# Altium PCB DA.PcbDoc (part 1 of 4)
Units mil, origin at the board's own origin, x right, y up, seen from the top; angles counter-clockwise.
Board outline 6588.03 x 5423.03 mil, 4 copper layers (Top Layer, GND, VCC, Bottom Layer); 506 components, 345 nets, 1676 pads, 350 vias.
Unrouted connection lines stored in the file: 30.
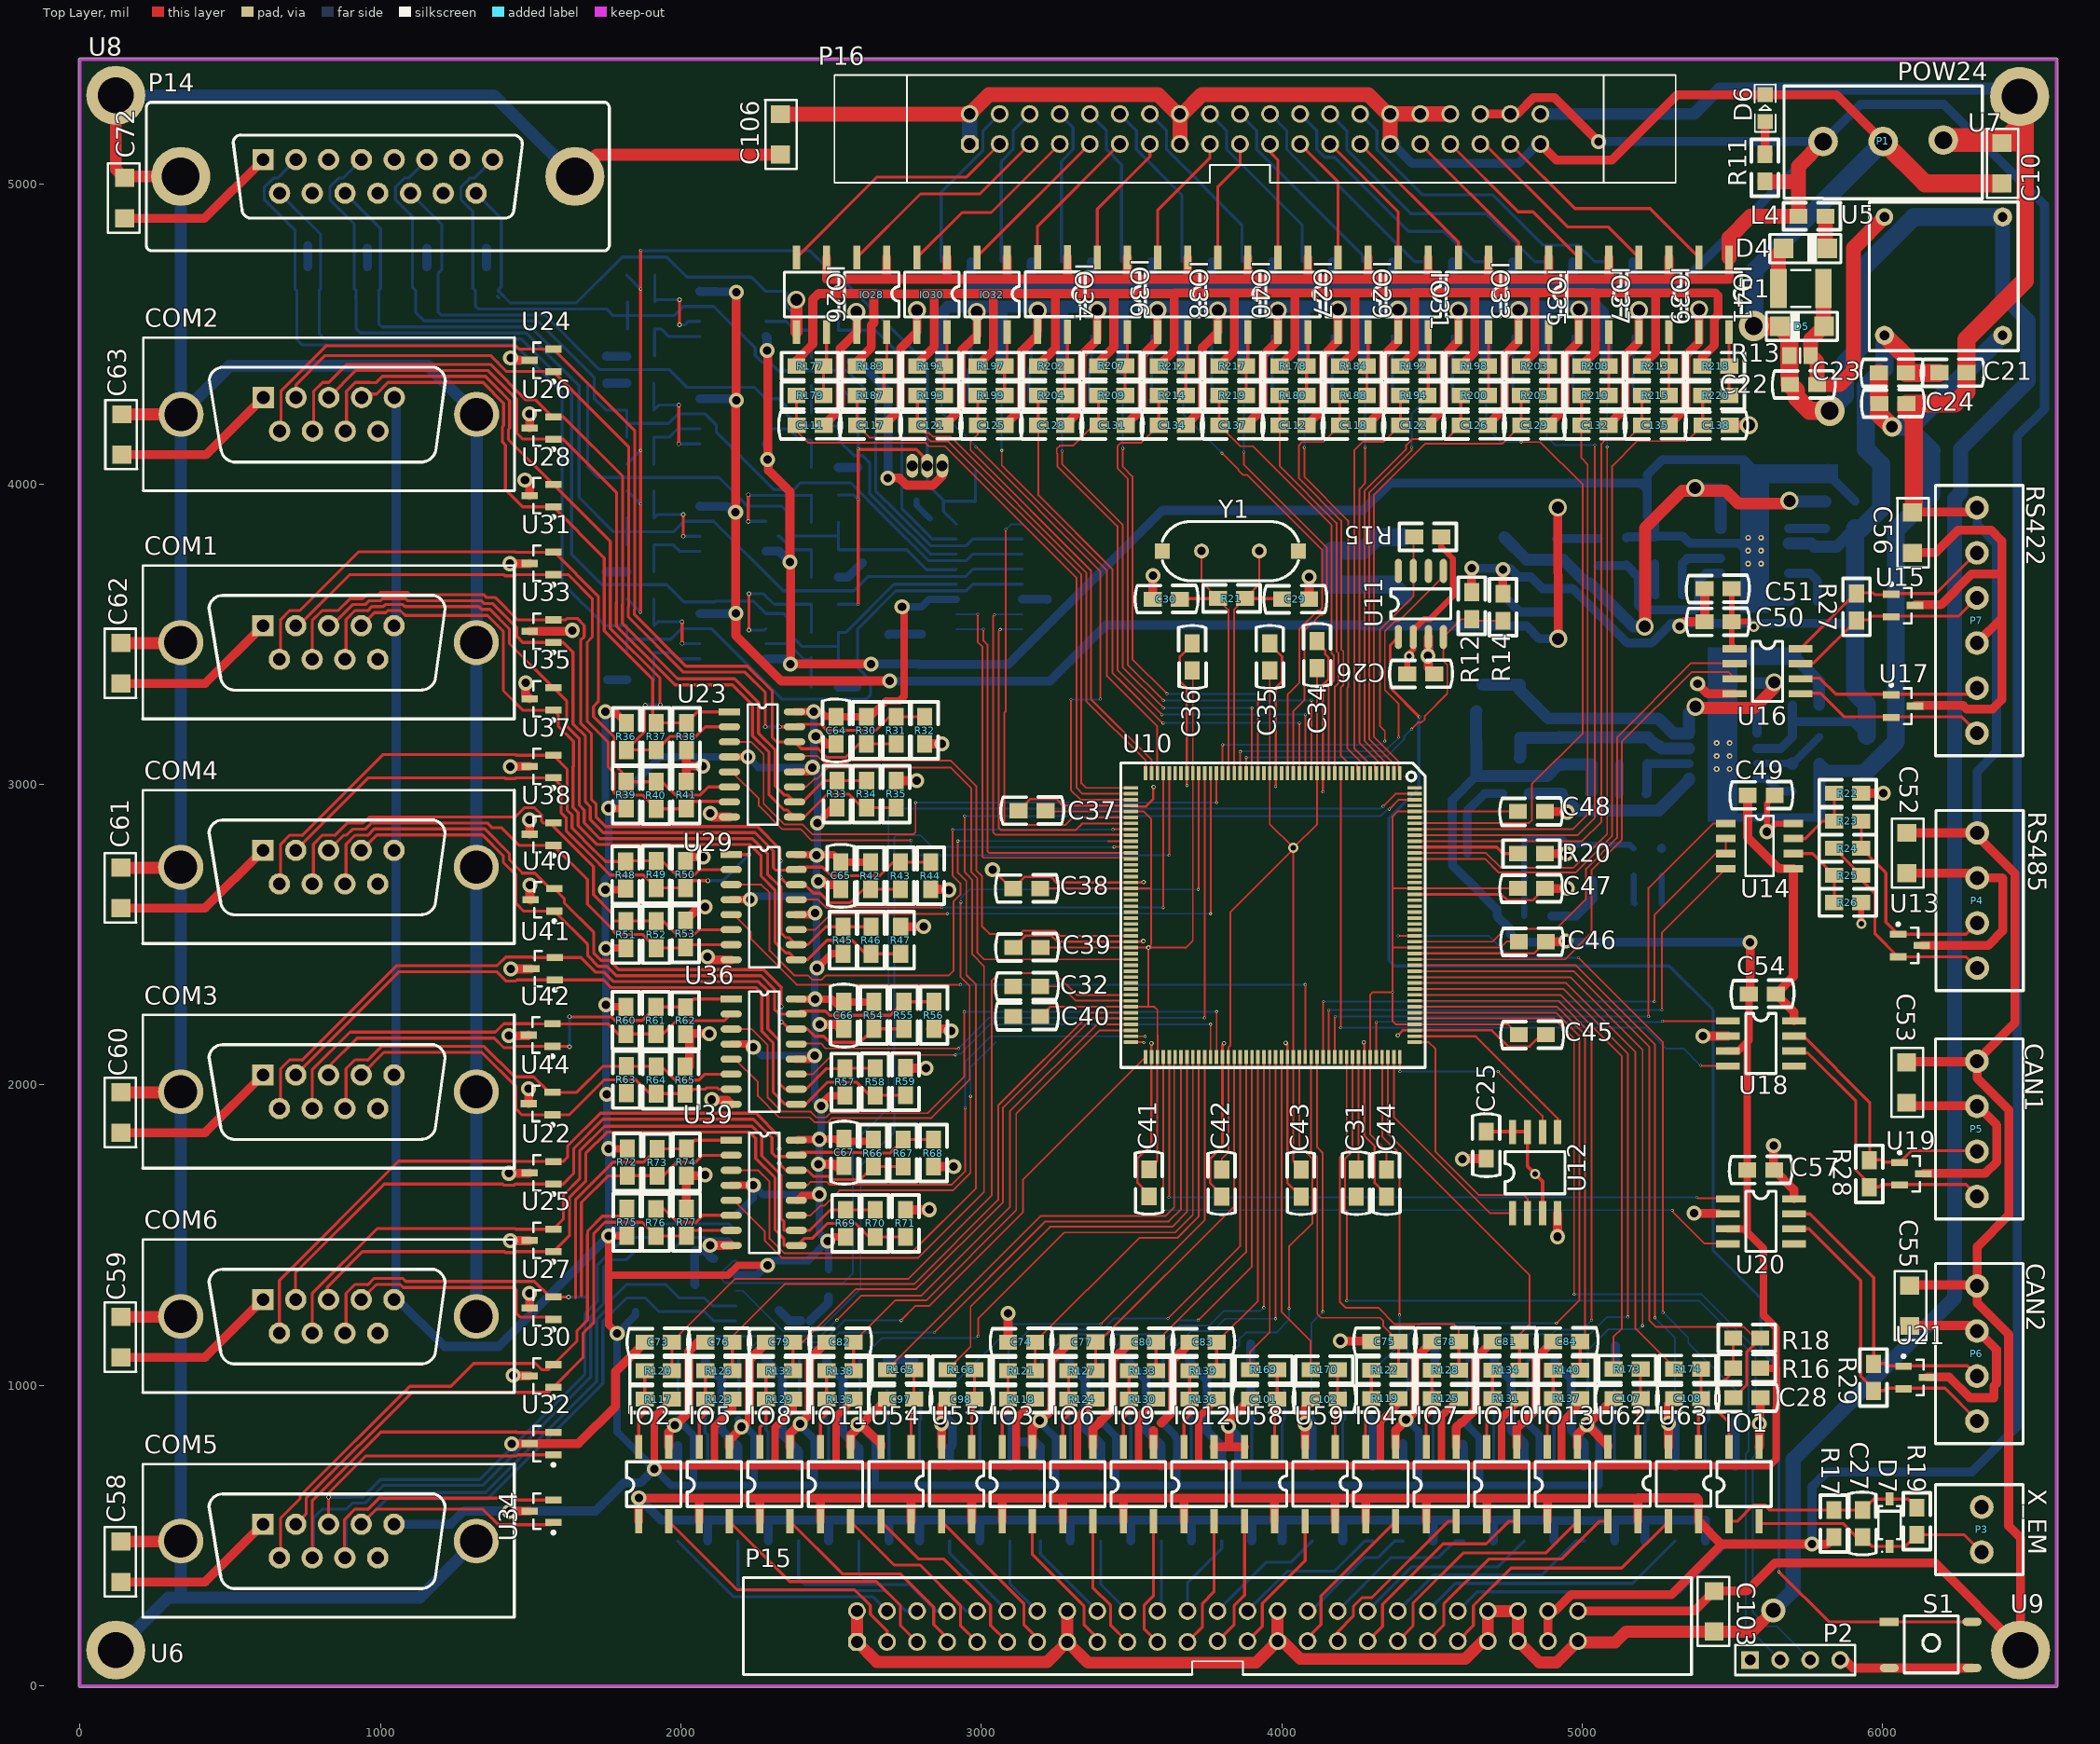
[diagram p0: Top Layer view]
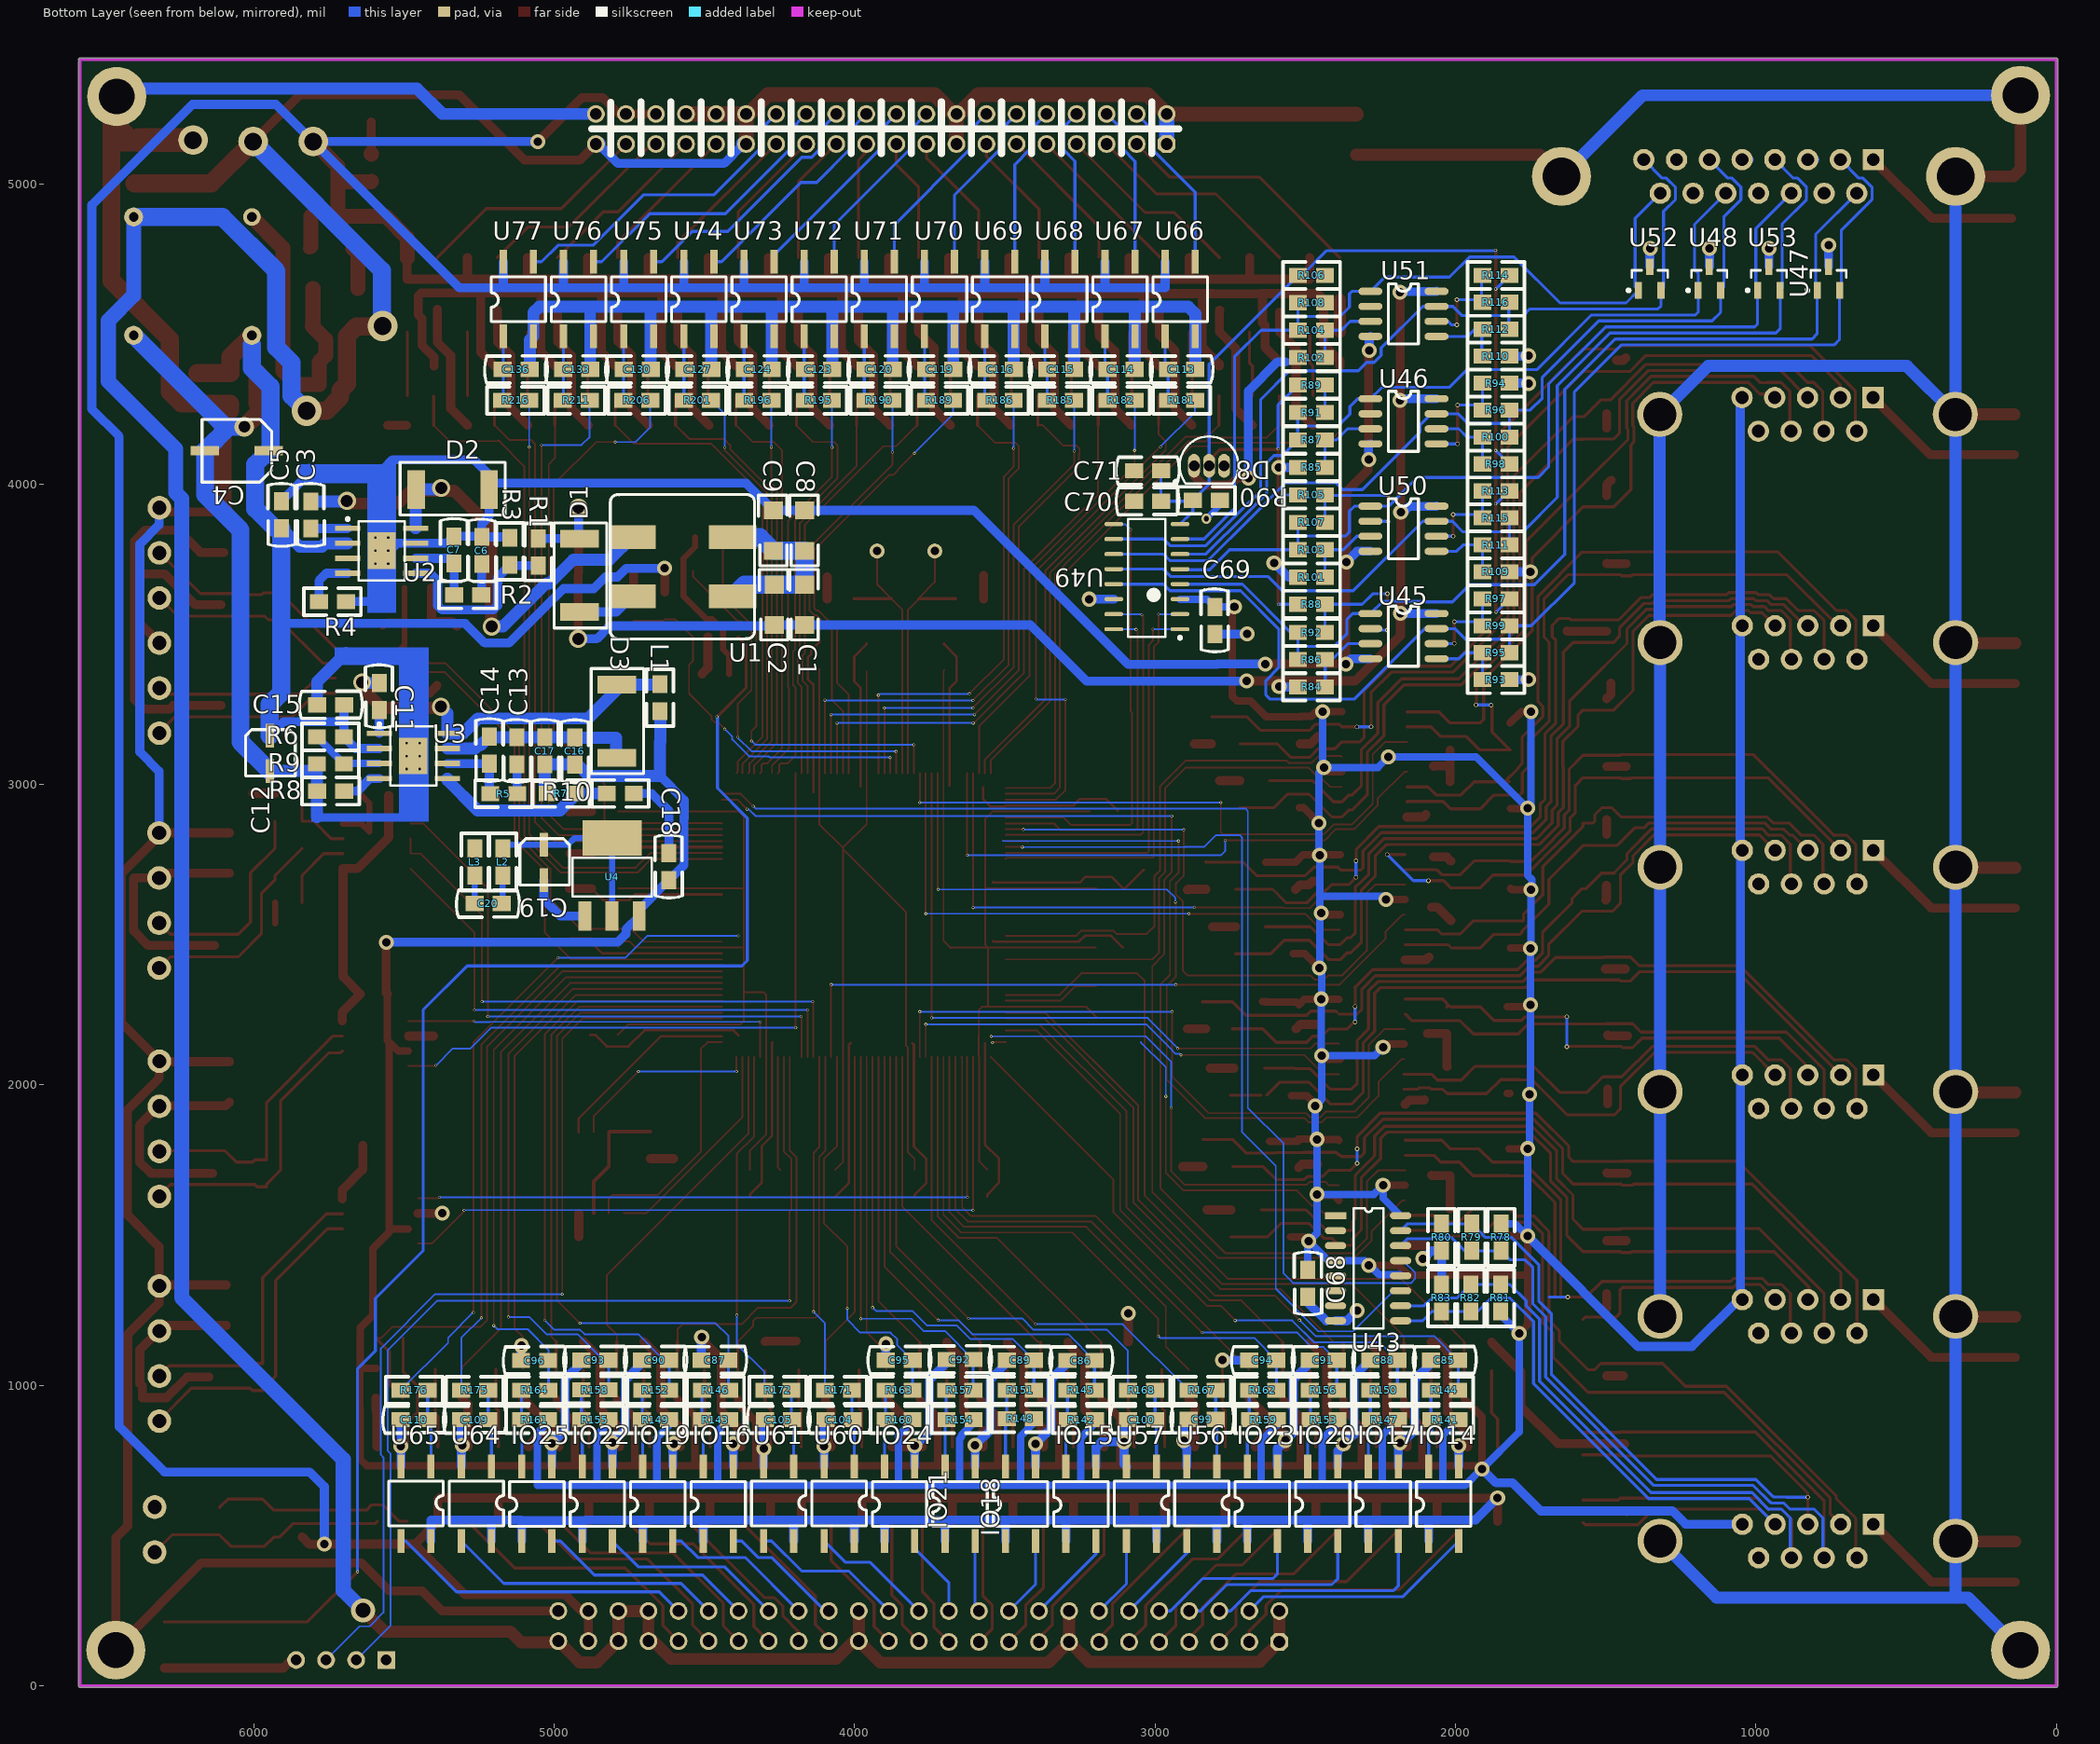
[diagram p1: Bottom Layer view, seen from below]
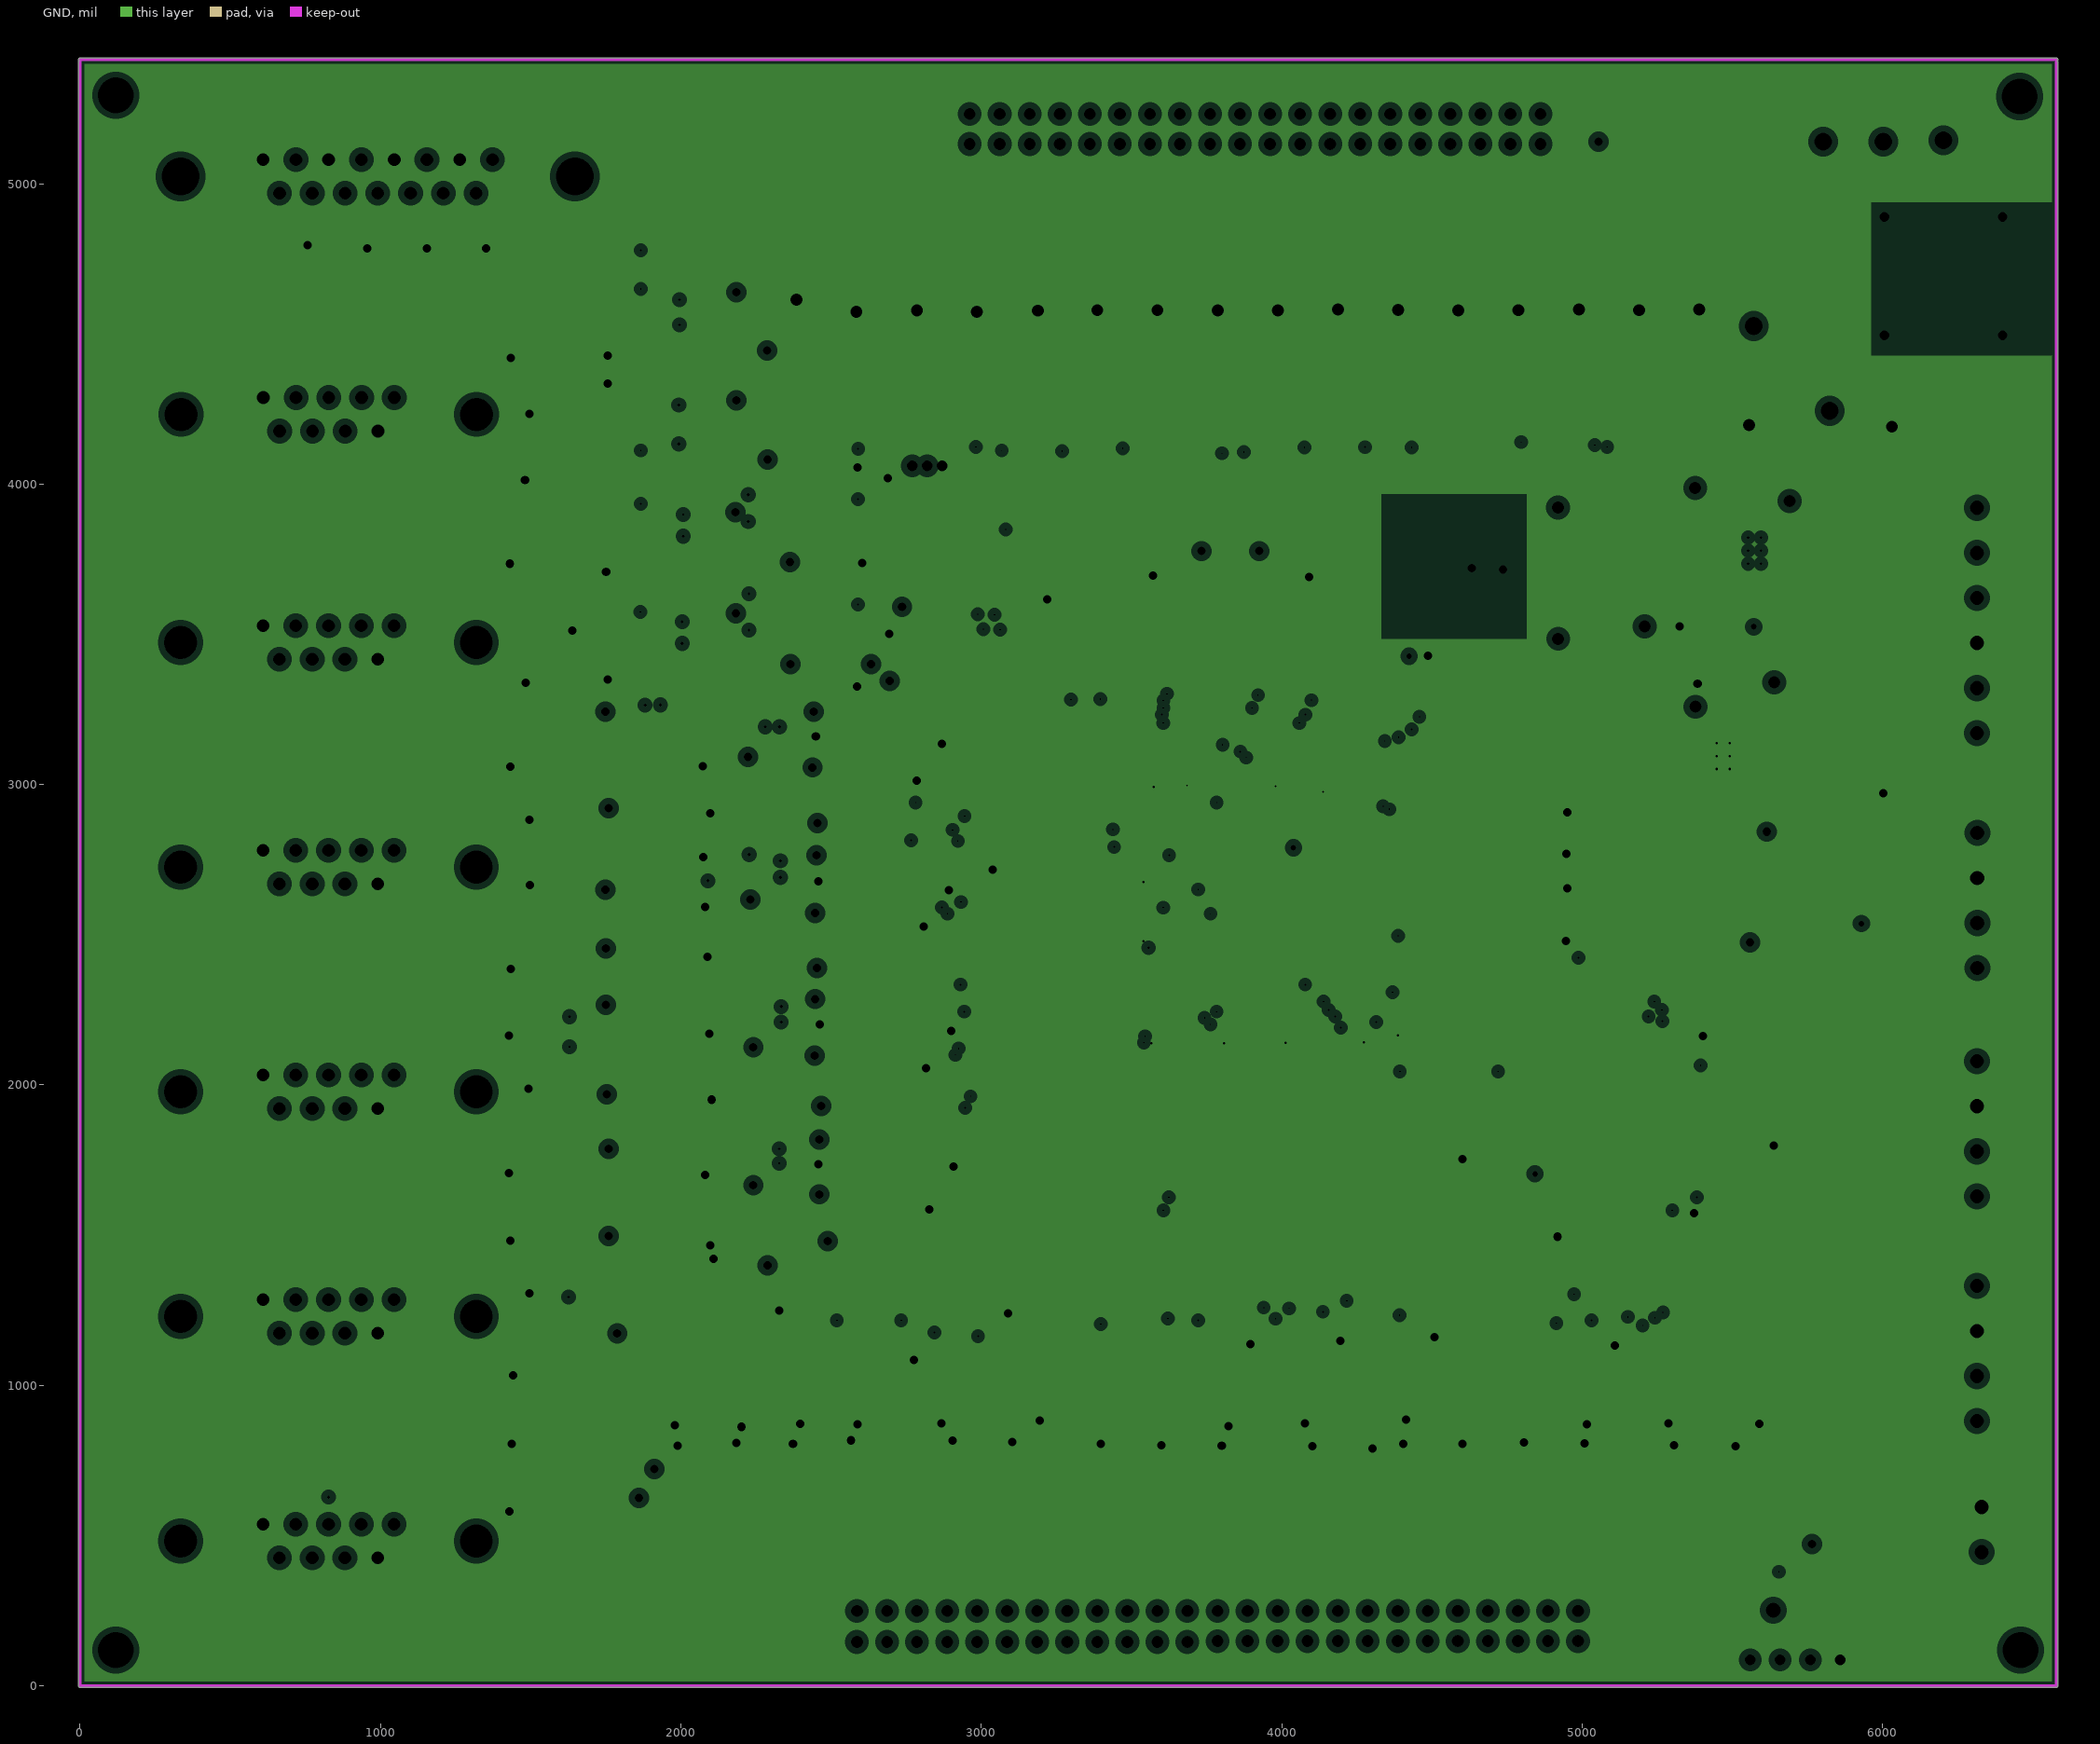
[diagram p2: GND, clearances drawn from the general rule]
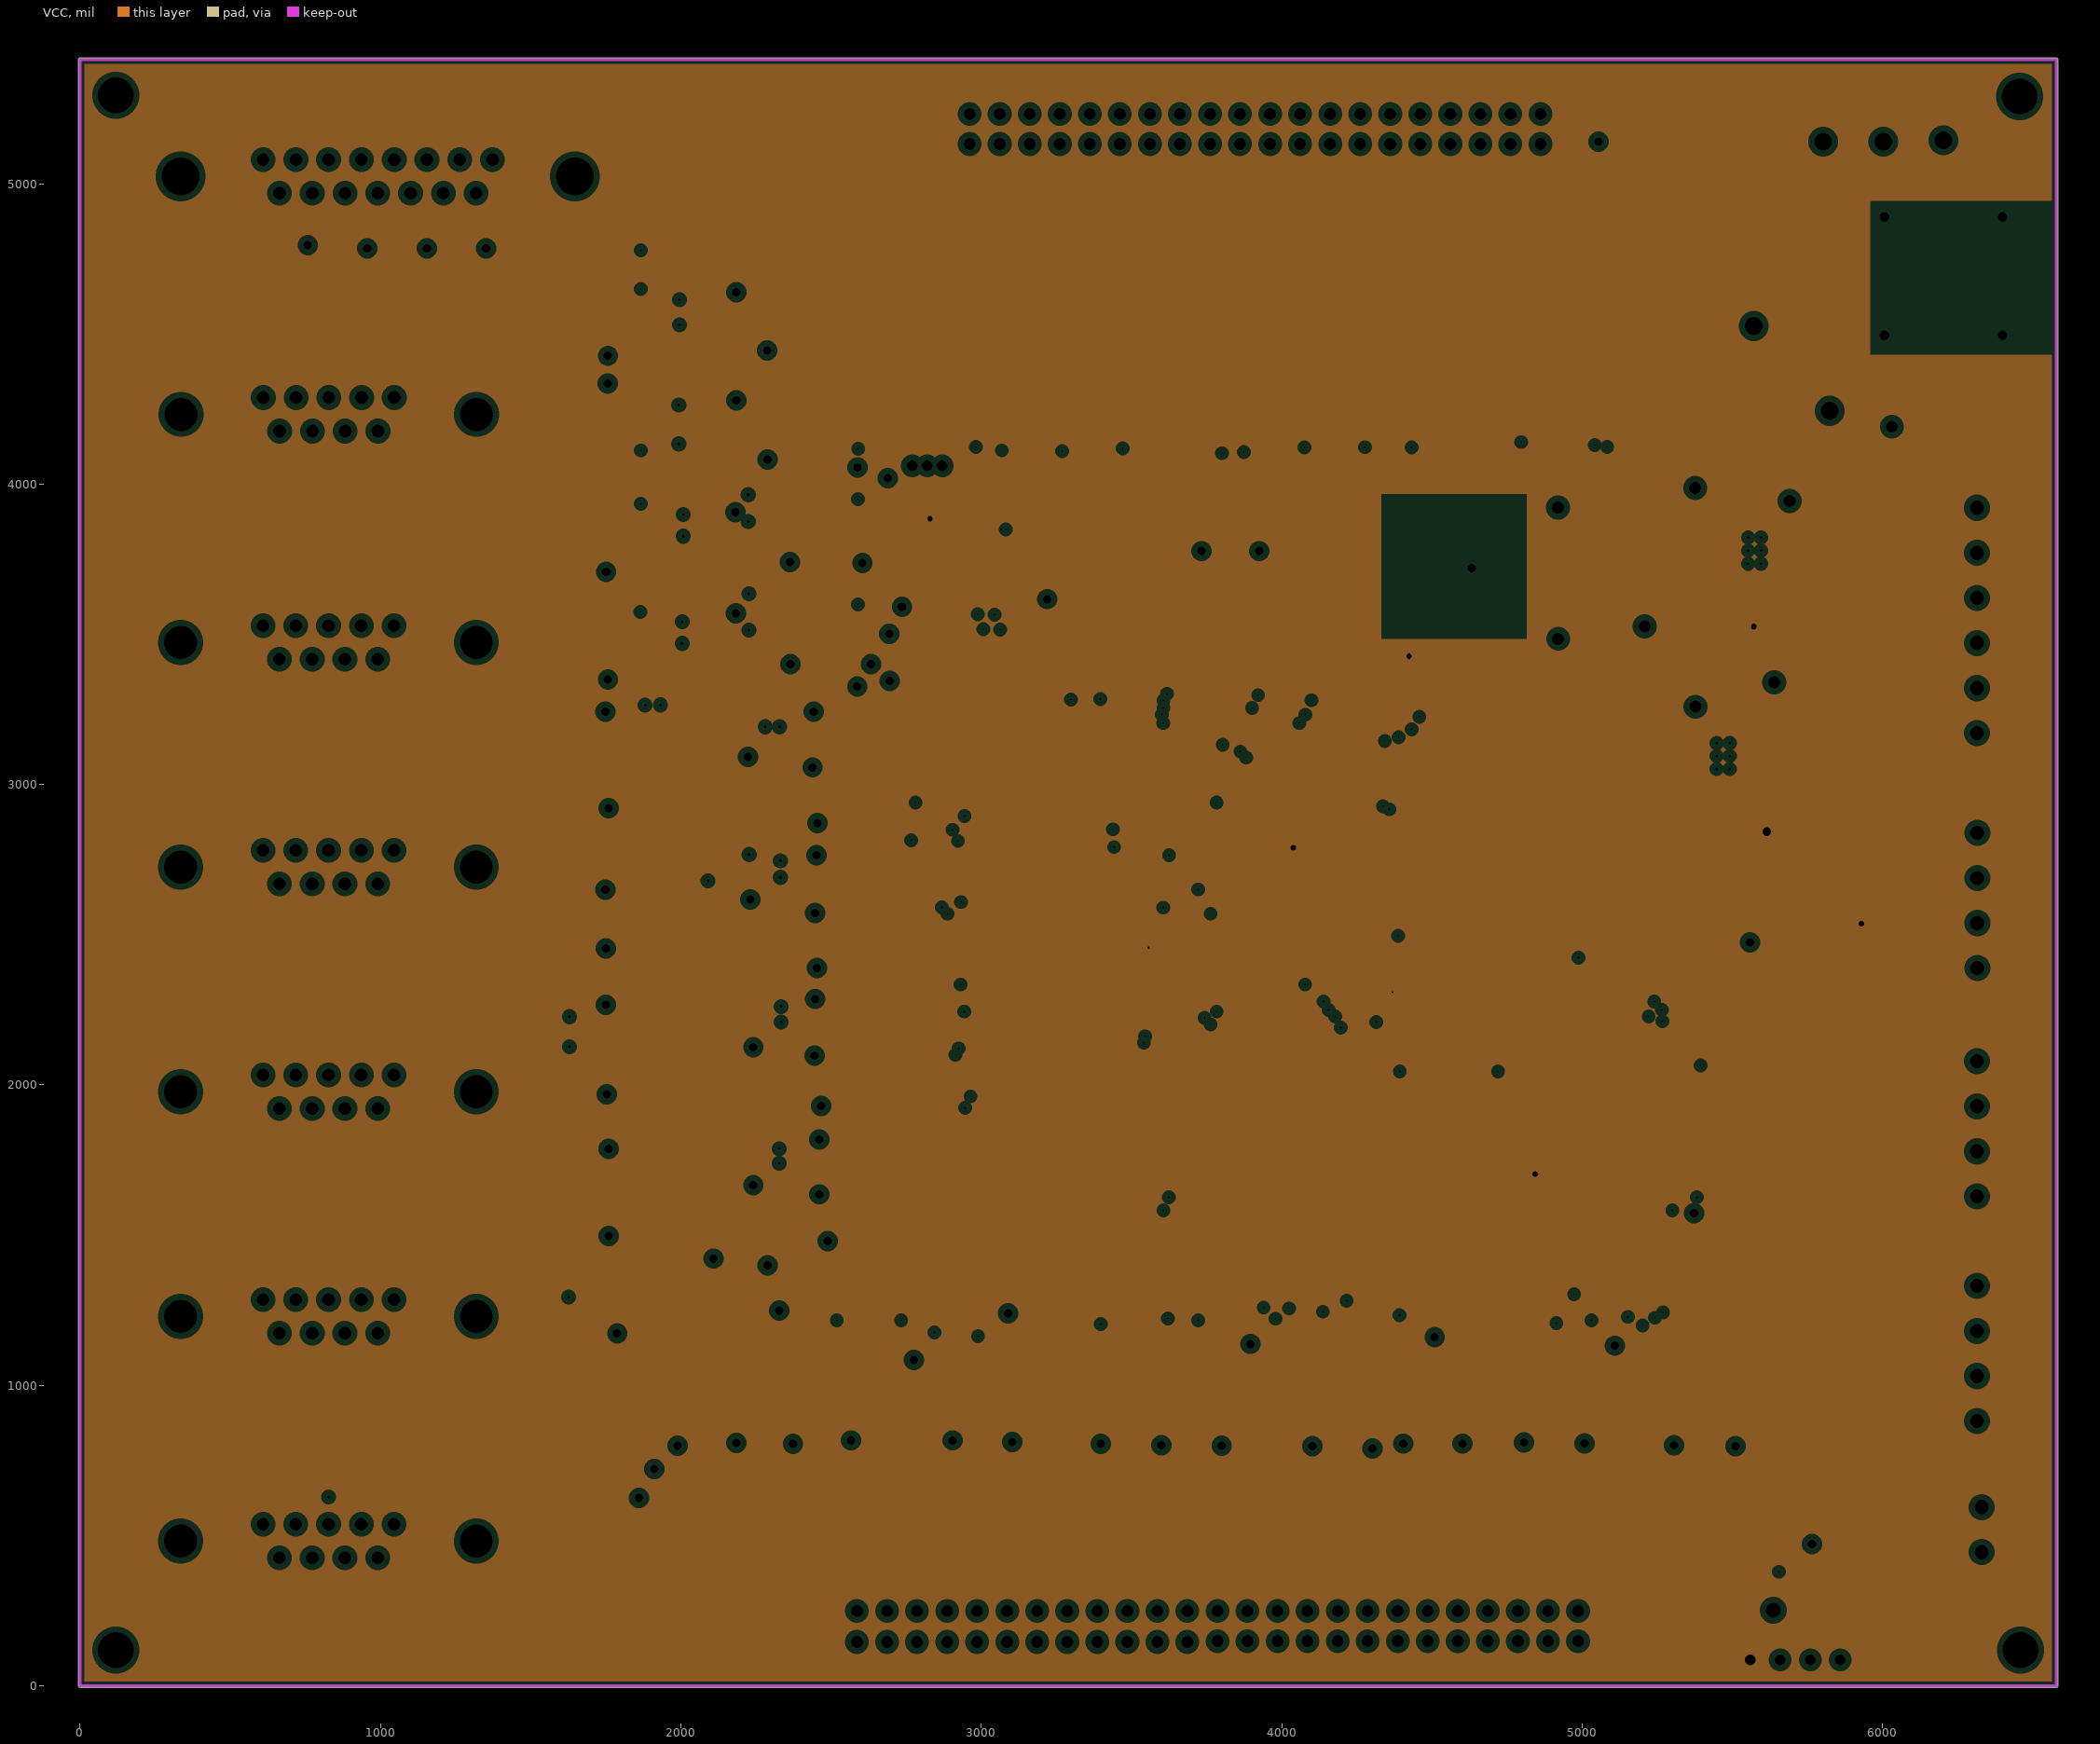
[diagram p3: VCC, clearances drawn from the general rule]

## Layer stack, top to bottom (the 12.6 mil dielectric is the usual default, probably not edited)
Top Layer: signal copper 1.4
Dielectric: core 12.6, FR-4, Dk 4.8
GND: plane copper 1.4, net GND
Dielectric: prepreg 12.6, FR-4, Dk 4.8
VCC: plane copper 1.4, net 3V3
Dielectric: core 12.6, FR-4, Dk 4.8
Bottom Layer: signal copper 1.4

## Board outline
-5.01,0 -5.01,5406 cw(c0,5406) -3.59,5409.5 cw(c0,5413) 0,5418.02 6578,5418.02 cw(c6578,5413) 6583.01,5413 cw(c6578,5413) 6580.21,5408.5 cw(c6578,5404) 6583.01,5404 6583.01,0 cw(c6578,0) 6578,-5.01 0,-5.01 cw(c0,0)

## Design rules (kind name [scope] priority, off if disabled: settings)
Clearance Clearance_U10 [InComponent('U10')] p1: gap=6
Clearance [All] p2: gap=10
ComponentClearance [All] p1 off: gap=10 collisioncheckmode=3 verticalgap=10 showdistances=FALSE
DiffPairsRouting [All] p1: maxlimit=10 minlimit=10 mostfreqgap=10 maxuncoupledlength=500
MinimumSolderMaskSliver [All] p1 off: minsoldermaskwidth=10
PlaneClearance [All] p1: clearance=20
PlaneConnect [All] p1: planeconnectstyle=Relief reliefexpansion=20 reliefentries=4 reliefconductorwidth=10 reliefairgap=10
PolygonConnect [All] p1: connectstyle=Relief reliefconductorwidth=10 reliefentries=4 polygonreliefangle="90 Angle" airgapwidth=10
RoutingVias [All] p1: holewidth=28 width=50 viastyle="Through Hole" minholewidth=28 minwidth=50 maxholewidth=28 maxwidth=50
SilkToSilkClearance [All] p1 off: silktosilkclearance=0
SilkToSolderMaskClearance [IsPad] p1 off: minsilkscreentomaskgap=6 clearancetoexposedcopper=TRUE
SolderMaskExpansion [All] p1: expansion=4
Width Width_PE [InNet('PE')] p1: maxlimit=100 minlimit=10 preferedwidth=30
Width Width_IOGND [InNet('IO_GND')] p2: maxlimit=60 minlimit=10 preferedwidth=50
Width Width_24V [InNet('24V0') or InNet('POW24')] p3: maxlimit=60 minlimit=10 preferedwidth=40
Width Width_5V [InNet('5V0')] p4: maxlimit=60 minlimit=10 preferedwidth=20
Width Width_GND [InNet('GND')] p5: maxlimit=60 minlimit=8 preferedwidth=30
Width Width_3V3 [InNet('3V3')] p6: maxlimit=20 minlimit=6 preferedwidth=15
Width [All] p7: maxlimit=60 minlimit=6 preferedwidth=10
21 further rules are at their usual default settings.

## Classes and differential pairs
component class 485_CAN_RJ45: C49 C50 C51 C52 C53 C54 C55 C56 C57 P4 P5 P6 P7 R22 R23 R24 R25 R26 R27 R28 R29 U13 U14 U15 U16 U17 U18 U19 U20 U21
component class AXIS_IO1: C73 C74 C75 C76 C77 C78 C79 C80 C81 C82 C83 C84 C85 C86 C87 C88 C89 C90 C91 C92 C93 C94 C95 C96 IO2 IO3 IO4 IO5 IO6 IO7 IO8 IO9 IO10 IO11 IO12 IO13 IO14 IO15 IO16 IO17 IO18 IO19 IO20 IO21 IO22 IO23 IO24 IO25 R117 R118 R119 R120 R121 R122 R123 R124 R125 R126 R127 R128 R129 R130 R131 R132 R133 R134 R135 R136 R137 R138 R139 R140 R141 R142 R143 R144 R145 R146 R147 R148 R149 R150 R151 R152 R153 R154 R155 R156 R157 R158 R159 R160 R161 R162 R163 R164
component class AXIS_IO2: C97 C98 C99 C100 C101 C102 C103 C104 C105 C106 C107 C108 C109 C110 P15 P16 R165 R166 R167 R168 R169 R170 R171 R172 R173 R174 R175 R176 U54 U55 U56 U57 U58 U59 U60 U61 U62 U63 U64 U65
component class DA: C69 C70 C71 C72 D8 P14 R84 R85 R86 R87 R88 R89 R90 R91 R92 R93 R94 R95 R96 R97 R98 R99 R100 R101 R102 R103 R104 R105 R106 R107 R108 R109 R110 R111 R112 R113 R114 R115 R116 U45 U46 U47 U48 U49 U50 U51 U52 U53
component class IO: C111 C112 C113 C114 C115 C116 C117 C118 C119 C120 C121 C122 C123 C124 C125 C126 C127 C128 C129 C130 C131 C132 C133 C134 C135 C136 C137 C138 IO26 IO27 IO28 IO29 IO30 IO31 IO32 IO33 IO34 IO35 IO36 IO37 IO38 IO39 IO40 IO41 R177 R178 R179 R180 R181 R182 R183 R184 R185 R186 R187 R188 R189 R190 R191 R192 R193 R194 R195 R196 R197 R198 R199 R200 R201 R202 R203 R204 R205 R206 R207 R208 R209 R210 R211 R212 R213 R214 R215 R216 R217 R218 R219 R220 U66 U67 U68 U69 U70 U71 U72 U73 U74 U75 U76 U77
component class MCU: C25 C26 C27 C28 C29 C30 C31 C32 C34 C35 C36 C37 C38 C39 C40 C41 C42 C43 C44 C45 C46 C47 C48 D7 IO1 P2 P3 R15 R16 R17 R18 R19 R20 R21 S1 U10 U11 U12 Y1
component class POW: C1 C2 C3 C4 C5 C6 C7 C8 C9 C10 C11 C12 C13 C14 C15 C16 C17 C18 C19 C20 C21 C22 C23 C24 D1 D2 D3 D4 D5 D6 F1 L1 L2 L3 L4 P1 R1 R2 R3 R4 R5 R6 R7 R8 R9 R10 R11 R12 R13 R14 U1 U2 U3 U4 U5 U6 U7 U8 U9
component class QEI: C58 C59 C60 C61 C62 C63 C64 C65 C66 C67 C68 COM1 COM2 COM3 COM4 COM5 COM6 R30 R31 R32 R33 R34 R35 R36 R37 R38 R39 R40 R41 R42 R43 R44 R45 R46 R47 R48 R49 R50 R51 R52 R53 R54 R55 R56 R57 R58 R59 R60 R61 R62 R63 R64 R65 R66 R67 R68 R69 R70 R71 R72 R73 R74 R75 R76 R77 R78 R79 R80 R81 R82 R83 U22 U23 U24 U25 U26 U27 U28 U29 U30 U31 U32 U33 U34 U35 U36 U37 U38 U39 U40 U41 U42 U43 U44
differential pair B3: +B3_P -B3_N
differential pair A0: +A0_P -A0_N
differential pair A1: +A1_P -A1_N
differential pair A2: +A2_P -A2_N
differential pair A3: +A3_P -A3_N
differential pair A4: +A4_P -A4_N
differential pair A5: +A5_P -A5_N
differential pair B0: +B0_P -B0_N
differential pair B1: +B1_P -B1_N
differential pair B2: +B2_P -B2_N
differential pair B4: +B4_P -B4_N
differential pair B5: +B5_P -B5_N
differential pair Z0: +Z0_P -Z0_N
differential pair Z1: +Z1_P -Z1_N
differential pair Z2: +Z2_P -Z2_N
differential pair Z3: +Z3_P -Z3_N
differential pair Z4: +Z4_P -Z4_N
differential pair Z5: +Z5_P -Z5_N

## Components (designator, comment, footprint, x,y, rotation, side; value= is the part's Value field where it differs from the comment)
C1 "Cap Pol1" X5R 4166,3531 r90 bottom
C2 "X5R陶瓷电容" X5R 4267,3531 r90 bottom
C3 "Cap" 0805_C 5810,3852 r90 bottom
C4 "Cap Pol1" "CAP 5.4" 6056,4111 r90 bottom
C5 "Cap" 0805_C 5908,3943 r270 bottom
C6 "Cap" 0805_C 5241,3824 r270 bottom
C7 "Cap" 0805_C 5333,3826 r270 bottom
C8 "Cap Pol1" X5R 4166,3778 r90 bottom
C9 "X5R陶瓷电容" X5R 4270,3778 r90 bottom
C10 "Cap" 1206 6397,5068 r270 top
C11 "Cap" 0805_C 5581.81,3248 r90 bottom
C12 "Cap Pol1" "CAP 4*5.4" 5946.81,3163 r180 bottom
C13 "Cap" 0805_C 5123.81,3157 r270 bottom
C14 "Cap" 0805_C 5215.81,3160 r270 bottom
C15 "Cap" 0805_C 5788.81,3265 r180 bottom
C16 "Cap" 0805_C 4930.81,3156 r270 bottom
C17 "Cap" 0805_C 5030.81,3157 r270 bottom
C18 "0.1uF" 0805_C 4618,2682 r90 bottom
C19 "220uF/16V" "CAP 4*5.4" 5034,2800 r180 bottom
C20 "0.1uF" 0805_C 5175,2604 r0 bottom
C21 "Cap" 0805_C 6279,4371 r180 top
C22 "Cap" 0805_C 5692,4331 r0 top
C23 "Cap" 0805_C 5987,4370 r0 top
C24 "Cap" 0805_C 5989,4268 r0 top
C25 "Cap" 0805_C 4680,1845 r270 top locked
C26 "Cap" 0805_C 4418,3368 r0 top
C27 "Cap" 0805_C 5933,495 r90 top
C28 "Cap" 0805_C 5593.91,958.44 r180 top
C29 "Cap" 0805_C 4091,3617 r180 top
C30 "Cap" 0805_C 3571,3617 r0 top
C31 "Cap" 0805_C 4248,1628 r90 top
C32 "Cap" 0805_C 3106,2328 r0 top
C34 "Cap" 0805_C 4117,3477 r270 top
C35 "Cap" 0805_C 3960,3470 r270 top
C36 "Cap" 0805_C 3702,3470 r270 top
C37 "Cap" 0805_C 3124,2913 r0 top
C38 "Cap" 0805_C 3106,2654 r0 top
C39 "Cap" 0805_C 3107,2458 r0 top
C40 "Cap" 0805_C 3106,2228 r0 top
C41 "Cap" 0805_C 3558,1629 r90 top locked
C42 "Cap" 0805_C 3800,1628 r90 top locked
C43 "Cap" 0805_C 4064,1628 r90 top locked
C44 "Cap" 0805_C 4348,1628 r90 top
C45 "Cap" 0805_C 4879,2167 r180 top
C46 "Cap" 0805_C 4879,2477 r180 top
C47 "Cap" 0805_C 4876,2654 r180 top
C48 "Cap" 0805_C 4876,2910 r180 top
C49 "Cap" 0805_C 5551,2964 r0 top
C50 "Cap" 0805_C 5497,3542 r180 top
C51 "Cap" 0805_C 5497,3652 r180 top
C52 "Cap" 1206 6081,2772 r270 top
C53 "Cap" 1206 6080,2008 r270 top
C54 "Cap" 0805_C 5555,2303 r0 top
C55 "Cap" 1206 6090,1265 r270 top
C56 "Cap" 1206 6099,3838 r270 top
C57 "Cap" 0805_C 5549,1717 r0 top
C58 "Cap" 1206 136,413 r90 top
C59 "Cap" 1206 136,1160.67 r90 top
C60 "Cap" 1206 136,1908.33 r90 top
C61 "Cap" 1206 136,2656 r90 top
C62 "Cap" 1206 136,3403.67 r90 top
C63 "Cap" 1206 139,4165 r90 top
C64 "0.1uF" 0805_C 2516.57,3225.36 r270 top
C65 "0.1uF" 0805_C 2532.16,2741.56 r270 top
C66 "0.1uF" 0805_C 2541.99,2276.5 r270 top
C67 "0.1uF" 0805_C 2543.19,1820.25 r270 top
C68 "0.1uF" 0805_C 2491,1385 r270 bottom
C69 "Cap" 0805_C 2801,3501 r90 bottom
C70 "Cap" 0805_C 3070,3943 r180 bottom
C71 "Cap" 0805_C 3070,4044 r180 bottom
C72 "Cap" 1206 148,4952 r90 top
C73 "Cap" 0805_C 1880,1144 r0 top
C74 "Cap" 0805_C 3088.73,1144 r0 top
C75 "Cap" 0805_C 4298.45,1146 r0 top
C76 "Cap" 0805_C 2081.45,1144 r0 top
C77 "Cap" 0805_C 3289.91,1144.44 r0 top
C78 "Cap" 0805_C 4499.91,1146 r0 top
C79 "Cap" 0805_C 2282.91,1144 r0 top
C80 "Cap" 0805_C 3491.64,1144 r0 top
C81 "Cap" 0805_C 4701.36,1146 r0 top
C82 "Cap" 0805_C 2484.36,1144 r0 top
C83 "Cap" 0805_C 3693.09,1144 r0 top
C84 "Cap" 0805_C 4902.82,1146 r0 top
C85 "Cap" 0805_C 2081,1084.06 r180 bottom
C86 "Cap" 0805_C 3291,1083.06 r180 bottom
C87 "Cap" 0805_C 4509.82,1084.06 r180 bottom
C88 "Cap" 0805_C 2283,1084.06 r180 bottom
C89 "Cap" 0805_C 3493,1084.06 r180 bottom
C90 "Cap" 0805_C 4708.15,1084.06 r180 bottom
C91 "Cap" 0805_C 2485,1084.06 r180 bottom
C92 "Cap" 0805_C 3694,1086.06 r180 bottom
C93 "Cap" 0805_C 4909,1084.06 r180 bottom
C94 "Cap" 0805_C 2686,1084.06 r180 bottom
C95 "Cap" 0805_C 3896,1084.06 r180 bottom
C96 "Cap" 0805_C 5110,1083.06 r180 bottom
C97 "Cap" 0805_C 2685.82,954 r0 top
C98 "Cap" 0805_C 2887.27,954 r0 top
C99 "Cap" 0805_C 2888,887.06 r180 bottom
C100 "Cap" 0805_C 3090,886.06 r180 bottom
C101 "Cap" 0805_C 3894.55,954 r0 top
C102 "Cap" 0805_C 4096,954 r0 top
C103 "Cap" 1206 5439,248 r90 top
C104 "Cap" 0805_C 4096,886.06 r180 bottom
C105 "Cap" 0805_C 4298,886.06 r180 bottom
C106 "Cap" 1206 2331,5164 r270 top
C107 "Cap" 0805_C 5104.27,956 r0 top
C108 "Cap" 0805_C 5305.73,956 r0 top
C109 "Cap" 0805_C 5309.72,886.06 r180 bottom
C110 "Cap" 0805_C 5511,886.06 r180 bottom
C111 "Cap" 0805_C 2475.41,4195.85 r180 top
C112 "Cap" 0805_C 4082.88,4195.85 r180 top
C113 "Cap" 0805_C 2866.09,4382 r0 bottom
C114 "Cap" 0805_C 3067.45,4382 r0 bottom
C115 "Cap" 0805_C 3268.82,4382 r0 bottom
C116 "Cap" 0805_C 3470.18,4382 r0 bottom
C117 "Cap" 0805_C 2676.34,4195.85 r180 top
C118 "Cap" 0805_C 4283.81,4195.85 r180 top
C119 "Cap" 0805_C 3671.55,4382 r0 bottom
C120 "Cap" 0805_C 3872.91,4382 r0 bottom
C121 "Cap" 0805_C 2877.28,4195.85 r180 top
C122 "Cap" 0805_C 4484.74,4195.85 r180 top
C123 "Cap" 0805_C 4074.27,4382 r0 bottom
C124 "Cap" 0805_C 4275.64,4382 r0 bottom
C125 "Cap" 0805_C 3078.21,4195.85 r180 top
C126 "Cap" 0805_C 4685.68,4195.85 r180 top
C127 "Cap" 0805_C 4477,4382 r0 bottom
C128 "Cap" 0805_C 3279.14,4195.85 r180 top
C129 "Cap" 0805_C 4886.61,4195.85 r180 top
C130 "Cap" 0805_C 4678.36,4382 r0 bottom
C131 "Cap" 0805_C 3480.08,4195.85 r180 top
C132 "Cap" 0805_C 5087.54,4195.85 r180 top
C133 "Cap" 0805_C 4879.73,4382 r0 bottom
C134 "Cap" 0805_C 3681.01,4195.85 r180 top
C135 "Cap" 0805_C 5288.48,4195.85 r180 top
C136 "Cap" 0805_C 5081.09,4382 r0 bottom
C137 "Cap" 0805_C 3881.94,4195.85 r180 top
C138 "Cap" 0805_C 5491.41,4195.85 r180 top
COM1 "DB9" DB9-180 827,3472.67 r180 top
COM2 "DB9" DB9-180 828,4232 r180 top
COM3 "DB9" DB9-180 827,1977.33 r180 top
COM4 "DB9" DB9-180 827,2725 r180 top
COM5 "DB9" DB9-180 827,482 r180 top
COM6 "DB9" DB9-180 827,1229.67 r180 top
D1 "B560C" DO-214AB 4915,3696 r90 bottom
D2 "B560C" DO-214AB 5338,3982 r0 bottom
D3 "B560C" DO-214AB 4792,3211 r90 bottom
D4 "40V/3A  SS34" DO-214AC 5742.89,4784 r0 top
D5 "MAJ48CA" DO-214AC 5731,4525 r180 top
D6 "LED0" VRCNC_LED_0805 5609,5206 r90 top
D7 "1N4007" SOD123 6023,543 r90 top
D8 "LM285Z-2.5" TO-92A 2820,4061 r270 bottom
F1 "3A" 1812 5728.05,4651 r0 top
IO1 "TLP185" "SO6 4PIN" 5488.91,547.56 r90 top
IO2 "TLP185" "SO6 4PIN" 1859.64,547.56 r90 top
IO3 "TLP185" "SO6 4PIN" 3069.39,547.56 r90 top
IO4 "TLP185" "SO6 4PIN" 4279.15,547.56 r90 top
IO5 "TLP185" "SO6 4PIN" 2061.26,547.56 r90 top
IO6 "TLP185" "SO6 4PIN" 3271.02,547.56 r90 top
IO7 "TLP185" "SO6 4PIN" 4480.78,547.56 r90 top
IO8 "TLP185" "SO6 4PIN" 2262.89,547.56 r90 top
IO9 "TLP185" "SO6 4PIN" 3472.65,547.56 r90 top
IO10 "TLP185" "SO6 4PIN" 4682.4,547.56 r90 top
IO11 "TLP185" "SO6 4PIN" 2464.51,547.56 r90 top
IO12 "TLP185" "SO6 4PIN" 3674.27,547.56 r90 top
IO13 "TLP185" "SO6 4PIN" 4884.03,547.56 r90 top
IO14 "TLP185" "SO6 4PIN" 2089,482.06 r90 bottom
IO15 "TLP185" "SO6 4PIN" 3296.41,482.06 r90 bottom
IO16 "TLP185" "SO6 4PIN" 4503.82,482.06 r90 bottom
IO17 "TLP185" "SO6 4PIN" 2290.24,482.06 r90 bottom
IO18 "TLP185" "SO6 4PIN" 3497.65,482.06 r90 bottom
IO19 "TLP185" "SO6 4PIN" 4705.06,482.06 r90 bottom
IO20 "TLP185" "SO6 4PIN" 2491.47,482.06 r90 bottom
IO21 "TLP185" "SO6 4PIN" 3698.88,482.06 r90 bottom
IO22 "TLP185" "SO6 4PIN" 4906.29,482.06 r90 bottom
IO23 "TLP185" "SO6 4PIN" 2692.71,482.06 r90 bottom
IO24 "TLP185" "SO6 4PIN" 3900.12,482.06 r90 bottom
IO25 "TLP185" "SO6 4PIN" 5107.53,482.06 r90 bottom
IO26 "TLP185" "SO6 4PIN" 2484.91,4754 r270 top
IO27 "TLP185" "SO6 4PIN" 4087.09,4754 r270 top
IO28 "TLP185" "SO6 4PIN" 2685.18,4754 r270 top
IO29 "TLP185" "SO6 4PIN" 4287.36,4754 r270 top
IO30 "TLP185" "SO6 4PIN" 2885.45,4754 r270 top
IO31 "TLP185" "SO6 4PIN" 4487.64,4754 r270 top
IO32 "TLP185" "SO6 4PIN" 3085.73,4754 r270 top
IO33 "TLP185" "SO6 4PIN" 4687.91,4754 r270 top
IO34 "TLP185" "SO6 4PIN" 3287,4755 r270 top
IO35 "TLP185" "SO6 4PIN" 4888.18,4754 r270 top
IO36 "TLP185" "SO6 4PIN" 3486.27,4754 r270 top
IO37 "TLP185" "SO6 4PIN" 5088.45,4754 r270 top
IO38 "TLP185" "SO6 4PIN" 3686.55,4754 r270 top
IO39 "TLP185" "SO6 4PIN" 5288.73,4754 r270 top
IO40 "TLP185" "SO6 4PIN" 3886.82,4754 r270 top
IO41 "TLP185" "SO6 4PIN" 5489,4754 r270 top
L1 "8.2uH" VRCNC_0805 4648,3334 r270 bottom
L2 "10uH" VRCNC_0805 5171,2787.27 r270 bottom
L3 "10uH" VRCNC_0805 5264,2787.27 r270 bottom
L4 "220uH" VRCNC_0805 5810,4891 r180 top
P1 "POW24" PT3_5.08 5802,5140 r0 top
P2 "Header 4" HDR1X4 5559,86 r0 top
P3 "X_EM" PT2_3.81 6329.75,445 r90 top locked
P4 "RS485" PT4_3.81 6315,2839 r270 top
P5 "CAN1" PT4_3.81 6314,2079 r270 top
P6 "CAN2" PT4_3.81 6314,1331 r270 top locked
P7 "RS422" PT6_3.81 6314,3921 r270 top
P14 "DA" DB15-180 991,5024 r180 top
P15 "Header 25X2" NJ-50 3786,199 r0 top locked
P16 "Header 20X2" NJ-40 2961,5132 r0 top
R1 "Res1" 0805_R 5053,3819 r270 bottom
R2 "Res1" 0805_R 5243,3631 r0 bottom
R3 "Res1" 0805_R 5147,3731 r90 bottom
R4 "Res1" 0805_R 5693,3609 r0 bottom
R5 "Res1" 0805_R 5122.81,2969 r0 bottom
R6 "Res2" 0805_R 5789.81,3159 r180 bottom
R7 "Res2" 0805_R 4931.81,2970 r0 bottom
R8 "Res1" 0805_R 5788.81,2978 r180 bottom
R9 "Res2" 0805_R 5789.81,3069 r180 bottom
R10 "Res2" 0805_R 4734.81,2970 r0 bottom
R11 "Res2" 0805_R 5608,5098 r270 top
R12 "Res2" 0805_R 4632,3550 r90 top
R13 "14D471K" 6-0805_N 5725,4428 r0 top
R14 "Res2" 0805_R 4736,3635 r270 top
R15 "Res2" 0805_R 4441,3824 r0 top
R16 "Res2" 0805_R 5502.91,1057.44 r0 top
R17 "Res2" 0805_R 5838,495 r90 top
R18 "Res2" 0805_R 5502.91,1157.44 r0 top
R19 "Res2" 0805_R 6114,503 r90 top
R20 "Res2" 0805_R 4876,2770 r180 top
R21 "Res2" 0805_R 3878,3619 r180 top
R22 "Res2" 0805_R 5839,2971 r0 top
R23 "Res2" 0805_R 5839,2878 r0 top
R24 "Res2" 0805_R 5839,2788 r0 top
R25 "Res2" 0805_R 5839,2698 r0 top
R26 "Res2" 0805_R 5929,2607 r180 top
R27 "Res2" 0805_R 5913,3636 r270 top
R28 "Res2" 0805_R 5956,1659 r90 top
R29 "Res2" 0805_R 5969,981 r90 top
R30 "Res2" 0805_R 2617.33,3225.36 r270 top
R31 "Res2" 0805_R 2716.31,3135.36 r90 top
R32 "Res2" 0805_R 2811.57,3225.36 r270 top
R33 "Res2" 0805_R 2519,2923 r90 top
R34 "Res2" 0805_R 2618,3013 r270 top
R35 "Res2" 0805_R 2717,2923 r90 top
R36 "Res2" 0805_R 1818,3205 r270 top
R37 "Res2" 0805_R 1918,3115 r90 top
R38 "Res2" 0805_R 2018,3205 r270 top
R39 "Res2" 0805_R 1817.44,2920 r90 top
R40 "Res2" 0805_R 1917.56,3009 r270 top
R41 "Res2" 0805_R 2017.57,2920 r90 top
R42 "Res2" 0805_R 2630.94,2741.35 r270 top
R43 "Res2" 0805_R 2730.94,2651.35 r90 top
R44 "Res2" 0805_R 2830.94,2741.35 r270 top
R45 "Res2" 0805_R 2539.23,2436.81 r90 top
R46 "Res2" 0805_R 2633.23,2526.81 r270 top
R47 "Res2" 0805_R 2731.23,2436.81 r90 top
R48 "Res2" 0805_R 1815.95,2653.81 r90 top
R49 "Res2" 0805_R 1917.95,2745.81 r270 top
R50 "Res2" 0805_R 2014.95,2654.81 r90 top
R51 "Res2" 0805_R 1817.23,2455.56 r90 top
R52 "Res2" 0805_R 1918.23,2545.56 r270 top
R53 "Res2" 0805_R 2015.23,2457.56 r90 top
R54 "Res2" 0805_R 2641.99,2276.93 r270 top
R55 "Res2" 0805_R 2741.99,2186.93 r90 top
R56 "Res2" 0805_R 2841.99,2276.93 r270 top
R57 "Res2" 0805_R 2545.99,1964.5 r90 top
R58 "Res2" 0805_R 2646.99,2055.5 r270 top
R59 "Res2" 0805_R 2747.99,1966 r90 top
R60 "Res2" 0805_R 1817.36,2260 r270 top
R61 "Res2" 0805_R 1917,2170 r90 top
R62 "Res2" 0805_R 2016,2259 r270 top
R63 "Res2" 0805_R 1818,1973 r90 top
R64 "Res2" 0805_R 1918,2061 r270 top
R65 "Res2" 0805_R 2014,1971 r90 top
R66 "Res2" 0805_R 2640.25,1818.25 r270 top
R67 "Res2" 0805_R 2740.25,1728.25 r90 top
R68 "Res2" 0805_R 2840.25,1818.25 r270 top
R69 "Res2" 0805_R 2548.25,1494.25 r90 top
R70 "Res2" 0805_R 2647,1584.25 r270 top
R71 "Res2" 0805_R 2747,1494.25 r90 top
R72 "Res2" 0805_R 1821,1788 r270 top
R73 "Res2" 0805_R 1921.12,1697.25 r90 top
R74 "Res2" 0805_R 2018.25,1788.25 r270 top
R75 "Res2" 0805_R 1820,1498 r90 top
R76 "Res2" 0805_R 1917,1587.25 r270 top
R77 "Res2" 0805_R 2019,1498 r90 top
R78 "Res2" 0805_R 1848,1538 r270 bottom
R79 "Res2" 0805_R 1946,1448 r90 bottom
R80 "Res2" 0805_R 2046,1538 r270 bottom
R81 "Res2" 0805_R 1850,1246 r90 bottom
R82 "Res2" 0805_R 1949,1336 r270 bottom
R83 "Res2" 0805_R 2047,1246 r90 bottom
R84 "Res2" 0805_R 2524,3324.89 r180 bottom
R85 "Res2" 0805_R 2524,4055.62 r180 bottom
R86 "Res2" 0805_R 2524,3416.23 r180 bottom
R87 "Res2" 0805_R 2524,4146.96 r180 bottom
R88 "Res2" 0805_R 2524,3600 r180 bottom
R89 "Res2" 0805_R 2524,4329.65 r180 bottom
R90 "Res2" 0805_R 2784,3946 r0 bottom
R91 "Res2" 0805_R 2434,4238.18 r0 bottom
R92 "Res2" 0805_R 2434,3506 r0 bottom
R93 "Res2" 0805_R 1820,3348.89 r0 bottom
R94 "Res2" 0805_R 1820,4335.95 r0 bottom
R95 "Res2" 0805_R 1820,3438.62 r0 bottom
R96 "Res2" 0805_R 1820,4246.22 r0 bottom
R97 "Res2" 0805_R 1820,3618.09 r0 bottom
R98 "Res2" 0805_R 1820,4066.75 r0 bottom
R99 "Res2" 0805_R 1910,3528.48 r180 bottom
R100 "Res2" 0805_R 1910,4156.62 r180 bottom
R101 "Res2" 0805_R 2524,3690.26 r180 bottom
R102 "Res2" 0805_R 2524,4420.99 r180 bottom
R103 "Res2" 0805_R 2524,3781.6 r180 bottom
R104 "Res2" 0805_R 2524,4512.33 r180 bottom
R105 "Res2" 0805_R 2524,3964.28 r180 bottom
R106 "Res2" 0805_R 2524,4695.02 r180 bottom
R107 "Res2" 0805_R 2434,3872.81 r0 bottom
R108 "Res2" 0805_R 2434,4603.55 r0 bottom
R109 "Res2" 0805_R 1820,3707.82 r0 bottom
R110 "Res2" 0805_R 1820,4425.69 r0 bottom
R111 "Res2" 0805_R 1820,3797.55 r0 bottom
R112 "Res2" 0805_R 1820,4515.42 r0 bottom
R113 "Res2" 0805_R 1820,3977.02 r0 bottom
R114 "Res2" 0805_R 1820,4694.89 r0 bottom
R115 "Res2" 0805_R 1910,3887.42 r180 bottom
R116 "Res2" 0805_R 1910,4605.28 r180 bottom
R117 "Res2" 0805_R 1880,954 r0 top
R118 "Res2" 0805_R 3088.73,954 r0 top
R119 "Res2" 0805_R 4298.45,956 r0 top
R120 "Res2" 0805_R 1880,1049 r0 top
R121 "Res2" 0805_R 3088.73,1049 r0 top
R122 "Res2" 0805_R 4298.45,1051 r0 top
R123 "Res2" 0805_R 2081.45,954 r0 top
R124 "Res2" 0805_R 3290.18,954 r0 top
R125 "Res2" 0805_R 4499.91,956 r0 top
R126 "Res2" 0805_R 2081.45,1049 r0 top
R127 "Res2" 0805_R 3290.18,1049 r0 top
R128 "Res2" 0805_R 4499.91,1051 r0 top
R129 "Res2" 0805_R 2282.91,954 r0 top
R130 "Res2" 0805_R 3491.64,954 r0 top
R131 "Res2" 0805_R 4701.36,956 r0 top
R132 "Res2" 0805_R 2282.91,1049 r0 top
R133 "Res2" 0805_R 3491.64,1049 r0 top
R134 "Res2" 0805_R 4701.36,1051 r0 top
R135 "Res2" 0805_R 2484.36,954 r0 top
R136 "Res2" 0805_R 3693.09,954 r0 top
R137 "Res2" 0805_R 4902.82,956 r0 top
R138 "Res2" 0805_R 2484.36,1049 r0 top
R139 "Res2" 0805_R 3693.09,1049 r0 top
R140 "Res2" 0805_R 4902.82,1051 r0 top
R141 "Res2" 0805_R 2080,886.06 r180 bottom
R142 "Res2" 0805_R 3290,886.06 r180 bottom
R143 "Res2" 0805_R 4508,886.06 r180 bottom
R144 "Res2" 0805_R 2081,984.06 r180 bottom
R145 "Res2" 0805_R 3291.59,984.06 r180 bottom
R146 "Res2" 0805_R 4508,984.06 r180 bottom
R147 "Res2" 0805_R 2281.28,886.06 r180 bottom
R148 "Res2" 0805_R 3493.35,889.35 r180 bottom
R149 "Res2" 0805_R 4708,886.06 r180 bottom
R150 "Res2" 0805_R 2282.76,984.06 r180 bottom
R151 "Res2" 0805_R 3493.35,984.06 r180 bottom
R152 "Res2" 0805_R 4707,984.06 r180 bottom
R153 "Res2" 0805_R 2482.56,886.06 r180 bottom
R154 "Res2" 0805_R 3694,886.06 r180 bottom
R155 "Res2" 0805_R 4909,886.06 r180 bottom
R156 "Res2" 0805_R 2484.53,984.06 r180 bottom
R157 "Res2" 0805_R 3695.12,984.06 r180 bottom
R158 "Res2" 0805_R 4909,985.06 r180 bottom
R159 "Res2" 0805_R 2683.83,886.06 r180 bottom
R160 "Res2" 0805_R 3897,886.06 r180 bottom
R161 "Res2" 0805_R 5110,886.06 r180 bottom
R162 "Res2" 0805_R 2686.29,984.06 r180 bottom
R163 "Res2" 0805_R 3896.88,984.06 r180 bottom
R164 "Res2" 0805_R 5109,984.06 r180 bottom
R165 "Res2" 0805_R 2685.82,1052.44 r0 top
R166 "Res2" 0805_R 2887.27,1052.44 r0 top
R167 "Res2" 0805_R 2888.06,984.06 r180 bottom
R168 "Res2" 0805_R 3089.82,984.06 r180 bottom
R169 "Res2" 0805_R 3894.55,1052.44 r0 top
R170 "Res2" 0805_R 4096,1052.44 r0 top
R171 "Res2" 0805_R 4098.65,984.06 r180 bottom
R172 "Res2" 0805_R 4300.41,984.06 r180 bottom
R173 "Res2" 0805_R 5104.27,1054.44 r0 top
R174 "Res2" 0805_R 5305.73,1054.44 r0 top
R175 "Res2" 0805_R 5309.23,984.06 r180 bottom
R176 "Res2" 0805_R 5511,984.06 r180 bottom
R177 "Res2" 0805_R 2474.59,4392.85 r180 top
R178 "Res2" 0805_R 4082.49,4392.85 r180 top
R179 "Res2" 0805_R 2474.59,4294.85 r180 top
R180 "Res2" 0805_R 4082.49,4294.85 r180 top
R181 "Res2" 0805_R 2866.09,4279 r0 bottom
R182 "Res2" 0805_R 3067.64,4279 r0 bottom
R183 "Res2" 0805_R 2675.58,4392.85 r180 top
R184 "Res2" 0805_R 4283.48,4392.85 r180 top
R185 "Res2" 0805_R 3269.18,4279 r0 bottom
R186 "Res2" 0805_R 3470.73,4279 r0 bottom
R187 "Res2" 0805_R 2675.58,4294.85 r180 top
R188 "Res2" 0805_R 4283.48,4294.85 r180 top
R189 "Res2" 0805_R 3672.27,4279 r0 bottom
R190 "Res2" 0805_R 3873.82,4279 r0 bottom
R191 "Res2" 0805_R 2876.57,4392.85 r180 top
R192 "Res2" 0805_R 4484.47,4392.85 r180 top
R193 "Res2" 0805_R 2876.57,4294.85 r180 top
R194 "Res2" 0805_R 4484.47,4294.85 r180 top
R195 "Res2" 0805_R 4075.36,4279 r0 bottom
R196 "Res2" 0805_R 4276.91,4279 r0 bottom
R197 "Res2" 0805_R 3077.55,4392.85 r180 top
R198 "Res2" 0805_R 4685.46,4392.85 r180 top
R199 "Res2" 0805_R 3077.55,4294.85 r180 top
R200 "Res2" 0805_R 4685.46,4294.85 r180 top
R201 "Res2" 0805_R 4478.45,4279 r0 bottom
R202 "Res2" 0805_R 3278.54,4392.85 r180 top
R203 "Res2" 0805_R 4886.44,4392.85 r180 top
R204 "Res2" 0805_R 3278.54,4294.85 r180 top
R205 "Res2" 0805_R 4886.44,4294.85 r180 top
R206 "Res2" 0805_R 4680,4279 r0 bottom
R207 "Res2" 0805_R 3479.53,4394.06 r180 top
R208 "Res2" 0805_R 5087.43,4392.85 r180 top
R209 "Res2" 0805_R 3479.53,4294.85 r180 top
R210 "Res2" 0805_R 5087.43,4294.85 r180 top
R211 "Res2" 0805_R 4881.54,4279 r0 bottom
R212 "Res2" 0805_R 3680.52,4392.85 r180 top
R213 "Res2" 0805_R 5288.42,4392.85 r180 top
R214 "Res2" 0805_R 3680.52,4294.85 r180 top
R215 "Res2" 0805_R 5288.42,4294.85 r180 top
R216 "Res2" 0805_R 5083.09,4279 r0 bottom
R217 "Res2" 0805_R 3881.51,4392.85 r180 top
R218 "Res2" 0805_R 5489.41,4392.85 r180 top
R219 "Res2" 0805_R 3881.51,4294.85 r180 top
R220 "Res2" 0805_R 5489.41,4294.85 r180 top
S1 "RESET" KEY 6022,213 r0 top
U1 "150uH" 共模电感154 4573,3725 r90 bottom
U2 "TPS54360" TSP54360 5574,3778 r180 bottom
U3 "TPS54360" TSP54360 5468.81,3095 r180 bottom
U4 "SPX1117-3.3" VRCNC_SOT223 4898,2570 r180 bottom
U5 "电感耦合器_1" "电感 18*10*10" 6006,4889 r0 top
U6 "Holl" M3 119,119 r90 top
U7 "Holl" M3 6456,5290 r180 top
U8 "Holl" M3 119,5294 r0 top
U9 "Holl" M3 6459,119 r90 top
U10 "STM32F407IGT6" stm32f407igt6 4393,3038 r270 top
U11 "SP708R" VRCNC_SOP8 4388,3491 r90 top
U12 "W25Q16" SOIC-8 4768,1573 r90 top locked
U13 "PSM712" SOT23-3 6091,2464 r0 top
U14 "SP3485" SOP-8 5478.5,2870.06 r0 top
U15 "PSM712" SOT23-3 6068,3596 r0 top
U16 "MAX3490" SO-8 5507,3452 r0 top
U17 "PSM712" SOT23-3 6068,3261 r0 top
U18 "TJA1050" SO-8 5485,2213 r0 top
U19 "PSM712" SOT23-3 6096,1704 r0 top
U20 "TJA1050" SO-8 5485,1621 r0 top
U21 "PSM712" SOT23-3 6109,1026 r0 top
U22 "PSM712" SOT23-3 1536,1707.76 r180 top
U23 "MC3486D" VRCNC_SOP16 2161.5,3242 r0 top
U24 "PSM712" SOT23-3 1536,4412 r180 top
U25 "PSM712" SOT23-3 1536,1482.41 r180 top
U26 "PSM712" SOT23-3 1536,4186.65 r180 top
U27 "PSM712" SOT23-3 1536,1257.06 r180 top
U28 "PSM712" SOT23-3 1536,3961.29 r180 top
U29 "MC3486D" VRCNC_SOP16 2167.23,2766.81 r0 top
U30 "PSM712" SOT23-3 1536,1031.71 r180 top
U31 "PSM712" SOT23-3 1536,3735.94 r180 top
U32 "PSM712" SOT23-3 1536,806.35 r180 top
U33 "PSM712" SOT23-3 1536,3510.59 r180 top
U34 "PSM712" SOT23-3 1536,581 r180 top
U35 "PSM712" SOT23-3 1536,3285.23 r180 top
U36 "MC3486D" VRCNC_SOP16 2167.23,2286 r0 top
U37 "PSM712" SOT23-3 1536,3059.88 r180 top
U38 "PSM712" SOT23-3 1536,2834.53 r180 top
U39 "MC3486D" VRCNC_SOP16 2167.23,1816 r0 top
U40 "PSM712" SOT23-3 1539,2616 r180 top
U41 "PSM712" SOT23-3 1541,2387 r180 top
U42 "PSM712" SOT23-3 1533,2166 r180 top
U43 "MC3486D" VRCNC_SOP16 2399,1565 r180 bottom
U44 "PSM712" SOT23-3 1533,1938 r180 top
U45 "LM258" VRCNC_SOP8 2283,3568.89 r180 bottom
U46 "LM258" VRCNC_SOP8 2283,4284 r180 bottom
U47 "PSM712" SOT23-3 758,4684 r90 bottom
U48 "PSM712" SOT23-3 1154.67,4684 r90 bottom
U49 "DAC8568" DAC8568 3027,3692 r0 bottom locked
U50 "LM258" VRCNC_SOP8 2283,3926.44 r180 bottom
U51 "LM258" VRCNC_SOP8 2283,4641.56 r180 bottom
U52 "PSM712" SOT23-3 1353,4684 r90 bottom
U53 "PSM712" SOT23-3 956.33,4684 r90 bottom
U54 "TLP187" "SO6 4PIN" 2766.14,795.56 r270 top
U55 "TLP187" "SO6 4PIN" 2967.77,795.56 r270 top
U56 "TLP187" "SO6 4PIN" 2793.94,730.06 r270 bottom
U57 "TLP187" "SO6 4PIN" 2995.18,730.06 r270 bottom
U58 "TLP187" "SO6 4PIN" 3975.9,795.56 r270 top
U59 "TLP187" "SO6 4PIN" 4177.52,795.56 r270 top
U60 "TLP187" "SO6 4PIN" 4001.35,730.06 r270 bottom
U61 "TLP187" "SO6 4PIN" 4202.59,730.06 r270 bottom
U62 "TLP187" "SO6 4PIN" 5185.66,795.56 r270 top
U63 "TLP187" "SO6 4PIN" 5387.28,795.56 r270 top
U64 "TLP187" "SO6 4PIN" 5208.76,730.06 r270 bottom
U65 "TLP187" "SO6 4PIN" 5410,730.06 r270 bottom
U66 "TLP187" "SO6 4PIN" 2966.09,4492 r90 bottom
U67 "TLP187" "SO6 4PIN" 3166.36,4492 r90 bottom
U68 "TLP187" "SO6 4PIN" 3366.64,4492 r90 bottom
U69 "TLP187" "SO6 4PIN" 3566.91,4492 r90 bottom
U70 "TLP187" "SO6 4PIN" 3767.18,4492 r90 bottom
U71 "TLP187" "SO6 4PIN" 3967.45,4492 r90 bottom
U72 "TLP187" "SO6 4PIN" 4167.73,4492 r90 bottom
U73 "TLP187" "SO6 4PIN" 4368,4492 r90 bottom
U74 "TLP187" "SO6 4PIN" 4568.27,4492 r90 bottom
U75 "TLP187" "SO6 4PIN" 4768.55,4492 r90 bottom
U76 "TLP187" "SO6 4PIN" 4968.82,4492 r90 bottom
U77 "TLP187" "SO6 4PIN" 5169.09,4492 r90 bottom
Y1 "8M" XTAL_US 3925,3777 r180 top

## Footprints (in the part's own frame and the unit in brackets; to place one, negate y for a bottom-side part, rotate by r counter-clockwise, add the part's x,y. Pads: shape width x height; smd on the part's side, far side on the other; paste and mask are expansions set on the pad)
6-0805_N [mm] "Chip Resistor, Body 2.0x1.2mm, IPC Medium Density"
  rect 1.2x1.4 smd: 1(-0.9,0) 2(0.9,0)
  silkscreen extent 0,-0.6 0,0.6, body extent -1.07,-0.7 1.07,0.7, height 0.7
0805_C [mil]
  rect 60x50 smd: 1(0,-0.06) 2(90,-0.06)
  silkscreen extent -59,-46 150,47
0805_R [mil]
  rect 60x50 smd: 1(0,-0.06) 2(90,-0.06)
  silkscreen extent -50,-45 140,45
1206 [mm]
  rect 1.52x1.6 smd: 1(-1.71,0) 2(1.71,0)
  silkscreen extent -2.92,-1.28 2.92,1.4
1812 [mm] "Chip Capacitor, Body 4.5x3.2mm, IPC High Density"
  rect 1.4x3.3 smd: 1(-1.9,0) 2(1.9,0)
  silkscreen extent -0.8,-1.55 0.8,1.55, body extent -2.4,-1.7 2.4,1.7, height 1.4
"CAP 4*5.4" [mm]
  rect 0.7x2 smd: 1(0,0) 2(0,-3)
  silkscreen extent -2.03,-3.43 2.16,0.51
"CAP 5.4" [mm]
  rect 0.8x2.4 smd: 1(0,-2.7) 2(0,2.7)
  silkscreen extent -2.65,-2.95 2.65,2.95
DAC8568 [mm]
  oval 1.6x0.35 smd: 1(-2.8,4.445) 2(-2.8,3.175) 3(-2.8,1.905) 4(-2.8,0.635) 5(-2.8,-0.635) 6(-2.8,-1.905) 7(-2.8,-3.175) 8(-2.8,-4.445) 9(2.8,-4.445) 10(2.8,-3.175) 11(2.8,-1.905) 12(2.8,-0.635) 13(2.8,0.635) 14(2.8,1.905) 15(2.8,3.175) 16(2.8,4.445)
  silkscreen extent -2.92,-4.88 1.58,5.29, body extent -2.26,-4.9 2.26,5.08, height 1.2
DB9-180 [mm]
  round 3.81 hole 2.794: 0(12.495,0) 10(-12.495,0)
  rect 1.8x1.8 hole 1.09: 1(5.54,-1.42)
  round 1.8 hole 1.09: 2(2.77,-1.42) 3(0,-1.42) 4(-2.77,-1.42) 5(-5.54,-1.42) 6(4.157,1.42) 7(1.385,1.42) 8(-1.385,1.42) 9(-4.157,1.42)
  silkscreen extent -15.7,-6.5 15.7,6.45
DB15-180 [mm]
  round 5 hole 3.2: 0(16.66,0) 16(-16.66,0)
  rect 1.8x1.8 hole 1.09: 1(9.697,-1.42)
  round 1.8 hole 1.09: 2(6.926,-1.42) 3(4.156,-1.42) 4(1.385,-1.42) 5(-1.385,-1.42) 6(-4.156,-1.42) 7(-6.926,-1.42) 8(-9.697,-1.42) 9(8.31,1.42) 10(5.54,1.42) 11(2.77,1.42) 12(0,1.42) 13(-2.77,1.42) 14(-5.54,1.42) 15(-8.31,1.42)
  silkscreen extent -19.57,-6.28 19.57,6.28
DO-214AB [mm]
  rect 1.49x3.27 smd: 1(-3.09,0) 2(3.09,0)
  silkscreen extent -4.44,-2.29 4.44,2.16
DO-214AC [mm]
  rect 1.655x1.67 smd: 1(1.865,0) 2(-1.865,0)
  silkscreen extent -3,-1.2 3,1.2, body extent -2.74,-1.4 2.74,1.4, height 2.3
HDR1X4 [mm]
  rect 1.5x1.5 hole 0.9: 1(0,0)
  round 1.5 hole 0.9: 2(2.54,0) 3(5.08,0) 4(7.62,0)
  silkscreen extent -1.27,-1.27 8.89,1.27
KEY [mm]
  rect 1.6x0.7 smd: 1(0,0)
  oval 1.6x0.7 smd: 1(7,0) 2(0,-3.9) 2(7,-3.9)
  silkscreen extent 1.27,-4.32 5.84,0.51
M3 [mm]
  round 5 hole 3: 1(0,0)
NJ-40 [mm]
  oct 1.5x1.5 hole 1: 1(0,0)
  round 1.5 hole 1: 2(0,2.54) 3(2.54,0) 4(2.54,2.54) 5(5.08,0) 6(5.08,2.54) 7(7.62,0) 8(7.62,2.54) 9(10.16,0) 10(10.16,2.54) 11(12.7,0) 12(12.7,2.54) 13(15.24,0) 14(15.24,2.54) 15(17.78,0) 16(17.78,2.54) 17(20.32,0) 18(20.32,2.54) 19(22.86,0) 20(22.86,2.54) 21(25.4,0) 22(25.4,2.54) 23(27.94,0) 24(27.94,2.54) 25(30.48,0) 26(30.48,2.54) 27(33.02,0) 28(33.02,2.54) 29(35.56,0) 30(35.56,2.54) 31(38.1,0) 32(38.1,2.54) 33(40.64,0) 34(40.64,2.54) 35(43.18,0) 36(43.18,2.54) 37(45.72,0) 38(45.72,2.54) 39(48.26,0) 40(48.26,2.54)
  silkscreen extent -11.43,-3.26 59.69,5.84, body extent -13.07,-3 61.89,5.9, height 23.26
NJ-50 [mm]
  oct 1.5x1.5 hole 1: 1(-30.48,-1.346)
  round 1.5 hole 1: 2(-30.48,1.27) 3(-27.94,-1.346) 4(-27.94,1.27) 5(-25.4,-1.346) 6(-25.4,1.27) 7(-22.86,-1.346) 8(-22.86,1.27) 9(-20.32,-1.346) 10(-20.32,1.27) 11(-17.78,-1.346) 12(-17.78,1.27) 13(-15.24,-1.346) 14(-15.24,1.27) 15(-12.7,-1.346) 16(-12.7,1.27) 17(-10.16,-1.346) 18(-10.16,1.27) 19(-7.62,-1.346) 20(-7.62,1.27) 21(-5.08,-1.346) 22(-5.08,1.27) 23(-2.54,-1.346) 24(-2.54,1.27) 25(0,-1.27) 26(0,1.27) 27(2.54,-1.27) 28(2.54,1.27) 29(5.08,-1.27) 30(5.08,1.27) 31(7.62,-1.27) 32(7.62,1.27) 33(10.16,-1.27) 34(10.16,1.27) 35(12.7,-1.27) 36(12.7,1.27) 37(15.24,-1.27) 38(15.24,1.27) 39(17.78,-1.27) 40(17.78,1.27) 41(20.32,-1.27) 42(20.32,1.27) 43(22.86,-1.27) 44(22.86,1.27) 45(25.4,-1.27) 46(25.4,1.27) 47(27.94,-1.27) 48(27.94,1.27) 49(30.48,-1.27) 50(30.48,1.27)
  silkscreen extent -40.08,-4.1 40.08,4.1
PT2_3.81 [mm]
  round 2 hole 1.2: 1(0,0) 2(3.81,0)
  silkscreen extent -1.9,-3.5 5.71,3.9
PT3_5.08 [mm]
  round 2.5 hole 1.5: 1(0,0) 2(5.08,0) 3(10.16,0.127)
  silkscreen extent -3.3,-4.83 13.46,4.7
PT4_3.81 [mm]
  round 2 hole 1.2: 1(0,0) 2(3.81,0) 3(7.62,0) 4(11.43,0)
  silkscreen extent -1.9,-3.5 13.33,3.9
PT6_3.81 [mm]
  round 2 hole 1.2: 1(0,0) 2(3.81,0) 3(7.62,0) 4(11.43,0) 5(15.24,0) 6(19.05,0)
  silkscreen extent -1.9,-3.5 20.95,3.9
"SO6 4PIN" [mil]
  rect 80x24 smd: 1(0,0) 3(0,-100) 4(248,-100) 6(248,0)
  silkscreen extent 49,-141 198,41
SO-8 [mil]
  rect 80x24 smd: 1(0,0) 2(0,-50) 3(0,-100) 4(0,-150) 5(220,-150) 6(220,-100) 7(220,-50) 8(220,0)
  silkscreen extent 60,-175 160,25, body extent -11,-172 225,21, height 64
SOD123 [mm] "Molded Diode, 2-Leads, Body 2.65x1.60mm, IPC Medium Density"
  rect 1.1x0.65 smd: 1(-2,0) 2(2,0)
  silkscreen extent -2.5,-0.95 1.4,0.95, body extent -1.4,-0.9 1.4,0.9, height 1.2
SOIC-8 [mil]
  rect 80x24 smd: 1(0,0) 2(0,-50.06) 3(0,-100.06) 4(0,-150.06) 5(270,-150) 6(270,-100) 7(270,-50) 8(270,0)
  silkscreen extent 65,-175 205,25
SOP-8 [mil]
  rect 65x25 smd: 1(0,0) 2(0,-50) 3(0,-100) 4(0,-150) 5(224.41,-150) 6(224.41,-100) 7(224.41,-50) 8(224.41,0)
  silkscreen extent 65,-175 159,25
SOT23-3 [mm] "SOT23, 3-Leads, Body 2.90x2.45mm, Pitch 0.95mm, IPC Medium Density"
  rect 1.4x0.6 smd: 1(-1,0.95) 2(-1,-0.95) 3(1,0)
  silkscreen extent -1.12,-1.5 0.7,1.92, body extent -0.7,-1.5 0.7,1.5, height 1
stm32f407igt6 [mm]
  rect 1.2x0.3 smd: 1(0,0) 2(0,-0.5) 3(0,-1) 4(0,-1.5) 5(0,-2) 6(0,-2.5) 7(0,-3) 8(0,-3.5) 9(0,-4) 10(0,-4.5) 11(0,-5) 12(0,-5.5) 13(0,-6) 14(0,-6.5) 15(0,-7) 16(0,-7.5) 17(0,-8) 18(0,-8.5) 19(0,-9) 20(0,-9.5) 21(0,-10) 22(0,-10.5) 23(0,-11) 24(0,-11.5) 25(0,-12) 26(0,-12.5) 27(0,-13) 28(0,-13.5) 29(0,-14) 30(0,-14.5) 31(0,-15) 32(0,-15.5) 33(0,-16) 34(0,-16.5) 35(0,-17) 36(0,-17.5) 37(0,-18) 38(0,-18.5) 39(0,-19) 40(0,-19.5) 41(0,-20) 42(0,-20.5) 43(0,-21) 44(0,-21.5) 89(24,-21.5) 90(24,-21) 91(24,-20.5) 92(24,-20) 93(24,-19.5) 94(24,-19) 95(24,-18.5) 96(24,-18) 97(24,-17.5) 98(24,-17) 99(24,-16.5) 100(24,-16) 101(24,-15.5) 102(24,-15) 103(24,-14.5) 104(24,-14) 105(24,-13.5) 106(24,-13) 107(24,-12.5) 108(24,-12) 109(24,-11.5) 110(24,-11) 111(24,-10.5) 112(24,-10) 113(24,-9.5) 114(24,-9) 115(24,-8.5) 116(24,-8) 117(24,-7.5) 118(24,-7) 119(24,-6.5) 120(24,-6) 121(24,-5.5) 122(24,-5) 123(24,-4.5) 124(24,-4) 125(24,-3.5) 126(24,-3) 127(24,-2.5) 128(24,-2) 129(24,-1.5) 130(24,-1) 131(24,-0.5) 132(24,0)
  rect 0.3x1.2 smd: 45(1.25,-22.75) 46(1.75,-22.75) 47(2.25,-22.75) 48(2.75,-22.75) 49(3.25,-22.75) 50(3.75,-22.75) 51(4.25,-22.75) 52(4.75,-22.75) 53(5.25,-22.75) 54(5.75,-22.75) 55(6.25,-22.75) 56(6.75,-22.75) 57(7.25,-22.75) 58(7.75,-22.75) 59(8.25,-22.75) 60(8.75,-22.75) 61(9.25,-22.75) 62(9.75,-22.75) 63(10.25,-22.75) 64(10.75,-22.75) 65(11.25,-22.75) 66(11.75,-22.75) 67(12.25,-22.75) 68(12.75,-22.75) 69(13.25,-22.75) 70(13.75,-22.75) 71(14.25,-22.75) 72(14.75,-22.75) 73(15.25,-22.75) 74(15.75,-22.75) 75(16.25,-22.75) 76(16.75,-22.75) 77(17.25,-22.75) 78(17.75,-22.75) 79(18.25,-22.75) 80(18.75,-22.75) 81(19.25,-22.75) 82(19.75,-22.75) 83(20.25,-22.75) 84(20.75,-22.75) 85(21.25,-22.75) 86(21.75,-22.75) 87(22.25,-22.75) 88(22.75,-22.75) 133(22.75,1.25) 134(22.25,1.25) 135(21.75,1.25) 136(21.25,1.25) 137(20.75,1.25) 138(20.25,1.25) 139(19.75,1.25) 140(19.25,1.25) 141(18.75,1.25) 142(18.25,1.25) 143(17.75,1.25) 144(17.25,1.25) 145(16.75,1.25) 146(16.25,1.25) 147(15.75,1.25) 148(15.25,1.25) 149(14.75,1.25) 150(14.25,1.25) 151(13.75,1.25) 152(13.25,1.25) 153(12.75,1.25) 154(12.25,1.25) 155(11.75,1.25) 156(11.25,1.25) 157(10.75,1.25) 158(10.25,1.25) 159(9.75,1.25) 160(9.25,1.25) 161(8.75,1.25) 162(8.25,1.25) 163(7.75,1.25) 164(7.25,1.25) 165(6.75,1.25) 166(6.25,1.25) 167(5.75,1.25) 168(5.25,1.25) 169(4.75,1.25) 170(4.25,1.25) 171(3.75,1.25) 172(3.25,1.25) 173(2.75,1.25) 174(2.25,1.25) 175(1.75,1.25) 176(1.25,1.25)
  silkscreen extent -0.86,-23.6 24.89,2.13
TO-92A [mm] "TO, Flat Index; 3 In-Line, Axial Leads; Body Dia. 4.5mm; Leads 0.51 x 0.48 mm (max)"
  oval 2x1 hole 0.9: 1(0,-1.27) 2(0,0) 3(0,1.27)
  silkscreen extent -2.48,-2.96 1.5,2.48, body extent -2.5,-2.5 1.5,2.5, height 6.86
TSP54360 [mm] "SOP, 8-Leads, Body 4.90x3.90mm, Pitch 1.27mm, Thermal Pad 3.10.2x2.40.2mm, IPC Medium Density"
  rect 2.15x0.45 smd: 1(-2.875,1.905) 2(-2.875,0.635) 3(-2.875,-0.635) 4(-2.875,-1.905) 5(2.875,-1.905) 6(2.875,-0.635) 7(2.875,0.635) 8(2.875,1.905)
  rect 2.4x3.1 smd: 9(0,0)
  silkscreen extent -3,-2.5 1.95,2.8, body extent -2,-2.5 2,2.5, height 1.7
VRCNC_0805 [mil]
  rect 60x50 smd: 1(0,0) 2(90,0)
  silkscreen extent -50,-45 140,45
VRCNC_LED_0805 [mil]
  rect 50x50 smd: 1(0,0) 2(90,0)
  silkscreen extent -33,-35 124,35
VRCNC_SOP8 [mil]
  oval 80x24 smd: 1(0,0) 2(0,-50) 3(0,-100) 4(0,-150) 5(220,-150) 6(220,-100) 7(220,-50) 8(220,0)
  silkscreen extent 60,-175 160,25
VRCNC_SOP16 [mm]
  rect 1.8x0.6 smd: 1(0,0)
  oval 1.8x0.6 smd: 2(0,-1.27) 3(0,-2.54) 4(0,-3.81) 5(0,-5.08) 6(0,-6.35) 7(0,-7.62) 8(0,-8.89) 9(5.499,-8.89) 10(5.499,-7.62) 11(5.499,-6.35) 12(5.499,-5.08) 13(5.499,-3.81) 14(5.499,-2.54) 15(5.499,-1.27) 16(5.499,0)
  silkscreen extent 1.53,-9.53 4.06,0.64
VRCNC_SOT223 [mm]
  rect 1.1x2.5 smd: 1(0,-0.2) 2(2.3,-0.2) 3(4.6,-0.2)
  rect 5x3 smd: 4(2.3,6.4)
  silkscreen extent -1.05,1.47 5.65,4.72
X5R [mm]
  rect 1.52x1.6 smd: 1(0,0) 2(3.42,0)
  silkscreen extent -1.27,-1.14 4.7,1.27
XTAL_US [mil]
  round 50 hole 28: 1(0,0) 2(192.13,0)
  rect 50x50 smd: ""(-130.32,0) ""(322.44,0)
  silkscreen extent -131,-98 323,98
共模电感154 [mm]
  rect 2x4 smd: 1(-2.5,4.25) 2(2.5,4.25) 3(-2.5,-4.25) 4(2.5,-4.25)
  silkscreen extent -6.1,-6.1 6.1,6.1
"电感 18*10*10" [mm]
  round 1.5 hole 0.8: 1(0,0)
  round 1.6 hole 0.8: 2(10,0) 3(0,-10) 4(10,-10)
  silkscreen extent -1.27,-11.3 11.3,1.27

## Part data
C1 C4 C8 C12: "Polarized Capacitor (Radial)"
C2 C9: library part "Cap Pol1", "Polarized Capacitor (Radial)"
C3 C5 C6 C7 C10 C11 C13 C14 C15 C16 C17 C21 C22 C23 C24 C25 C26 C27 C28 C29 C30 C31 C32 C34 C35 C36 C37 C38 C39 C40 C41 C42 C43 C44 C45 C46 C47 C48 C49 C50 C51 C52 C53 C54 C55 C56 C57 C58 C59 C60 C61 C62 C63 C69 C70 C71 C72 C73 C74 C75 C76 C77 C78 C79 C80 C81 C82 C83 C84 C85 C86 C87 C88 C89 C90 C91 C92 C93 C94 C95 C96 C97 C98 C99 C100 C101 C102 C103 C104 C105 C106 C107 C108 C109 C110 C111 C112 C113 C114 C115 C116 C117 C118 C119 C120 C121 C122 C123 C124 C125 C126 C127 C128 C129 C130 C131 C132 C133 C134 C135 C136 C137 C138: "Capacitor"
C18 C20 C64 C65 C66 C67 C68: library part CAP, "Capacitor"
C19: library part "CAPACITOR POL", "Capacitor"
D1 D2 D3 D4 D7: library part "Diode 1N4007", "1 Amp General Purpose Rectifier"
D5 D8: library part "DIODE SCHOTTKY", "Schottky Diode"
D6: "Typical INFRARED GaAs LED"
F1: library part "Fuse 1", "Fuse"
IO1 IO2 IO3 IO4 IO5 IO6 IO7 IO8 IO9 IO10 IO11 IO12 IO13 IO14 IO15 IO16 IO17 IO18 IO19 IO20 IO21 IO22 IO23 IO24 IO25 IO26 IO27 IO28 IO29 IO30 IO31 IO32 IO33 IO34 IO35 IO36 IO37 IO38 IO39 IO40 IO41: "4-Pin Phototransistor Optocoupler"
L1 L2 L3 L4: library part INDUCTOR
P1: library part "Header 3", "Header, 3-Pin"
P2: "Header, 4-Pin"
P3: library part "Header 2", "Header, 2-Pin"
P4 P5 P6: library part "Header 4", "Header, 4-Pin"
P7: library part "Header 6", "Header, 6-Pin"
P14: library part DB15M
P15: "Header, 25-Pin, Dual row"
P16: "Header, 20-Pin, Dual row"
R1 R2 R3 R4 R5 R6 R7 R8 R9 R10 R11 R12 R14 R15 R16 R17 R18 R19 R20 R21 R22 R23 R24 R25 R26 R27 R28 R29 R30 R31 R32 R33 R34 R35 R36 R37 R38 R39 R40 R41 R42 R43 R44 R45 R46 R47 R48 R49 R50 R51 R52 R53 R54 R55 R56 R57 R58 R59 R60 R61 R62 R63 R64 R65 R66 R67 R68 R69 R70 R71 R72 R73 R74 R75 R76 R77 R78 R79 R80 R81 R82 R83 R84 R85 R86 R87 R88 R89 R90 R91 R92 R93 R94 R95 R96 R97 R98 R99 R100 R101 R102 R103 R104 R105 R106 R107 R108 R109 R110 R111 R112 R113 R114 R115 R116 R117 R118 R119 R120 R121 R122 R123 R124 R125 R126 R127 R128 R129 R130 R131 R132 R133 R134 R135 R136 R137 R138 R139 R140 R141 R142 R143 R144 R145 R146 R147 R148 R149 R150 R151 R152 R153 R154 R155 R156 R157 R158 R159 R160 R161 R162 R163 R164 R165 R166 R167 R168 R169 R170 R171 R172 R173 R174 R175 R176 R177 R178 R179 R180 R181 R182 R183 R184 R185 R186 R187 R188 R189 R190 R191 R192 R193 R194 R195 R196 R197 R198 R199 R200 R201 R202 R203 R204 R205 R206 R207 R208 R209 R210 R211 R212 R213 R214 R215 R216 R217 R218 R219 R220: "Resistor"
R13: library part "Res Varistor", "Varistor (Voltage-Sensitive Resistor)"
S1: library part COMPONENT_4
U1: library part 电感耦合器
U4: library part SPX1117
U11: library part SP706
U12: library part W25X16, "W25X16;SST25VF016;MX25L1605"
U14: library part SN75176
U23 U29 U36 U39 U43: library part SN75175
U45 U46 U50 U51: library part LF353
U54 U55 U56 U57 U58 U59 U60 U61 U62 U63 U64 U65 U66 U67 U68 U69 U70 U71 U72 U73 U74 U75 U76 U77: "<150mA"
Y1: library part XTAL, "Crystal Oscillator"

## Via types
v1: diameter 10, hole 6, Top Layer to Bottom Layer, 112 vias
v2: diameter 50, hole 28, Top Layer to GND, 68 vias
v3: diameter 50, hole 28, Top Layer to Bottom Layer, 46 vias
v4: diameter 50, hole 28, GND to Bottom Layer, 36 vias
v5: diameter 15, hole 10, Top Layer to Bottom Layer, 28 vias
v6: diameter 60, hole 40, Top Layer to GND, 17 vias
v7: diameter 19.68, hole 7.87, Top Layer to Bottom Layer, 12 vias
v8: diameter 15, hole 8, Top Layer to GND, 8 vias
v9: diameter 60, hole 40, Top Layer to Bottom Layer, 7 vias
v10: diameter 34, hole 18, Top Layer to VCC, 4 vias
v11: diameter 10, hole 6, Top Layer to GND, 3 vias
v12: diameter 100, hole 60, Top Layer to Bottom Layer, 2 vias
v13: diameter 36, hole 20, Top Layer to VCC, 1 vias
v14: diameter 15, hole 8, Top Layer to VCC, 1 vias
v15: diameter 10, hole 6, Top Layer to VCC, 1 vias
v16: diameter 65, hole 40, Top Layer to Bottom Layer, 1 vias
v17: diameter 50, hole 28, Top Layer to VCC, 1 vias
v18: diameter 34, hole 18, VCC to Bottom Layer, 1 vias
v19: diameter 80, hole 50, Top Layer to Bottom Layer, 1 vias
